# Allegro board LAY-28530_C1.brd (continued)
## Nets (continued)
EC1_RXD0: R59.2 U21.V2(EC1_RXD0/GPIO3_21)
EC1_RXD1: R55.2 U21.V1(EC1_RXD1/GPIO3_20)
EC1_RXD1/CFG_MODE0: R55.1 R214.2 U5.25(RXD1/CFG_MODE0)
EC1_RXD2: R53.2 U21.U1(EC1_RXD2/GPIO3_19)
EC1_RXD2/CFG_MODE1: R53.1 R210.2 U5.24(RXD2/CFG_MODE1)
EC1_RXD3: R49.2 U21.T2(EC1_RXD3/GPIO3_18)
EC1_RXD3/CFG_MODE2: R49.1 R207.2 U5.23(RXD3/CFG_MODE2)
EC1_TXC: R285.1 U5.21(TXC)
EC1_TXCTL: R288.1 U5.20(TXCTL)
EC1_TXD0: R296.1 U5.19(TXD0)
EC1_TXD1: R287.1 U5.18(TXD1)
EC1_TXD2: R295.1 U5.17(TXD2)
EC1_TXD3: R286.1 U5.16(TXD3)
EC1_VDDREG: C235.2 C251.1 R225.2 U5.31(VDD_REG)
EMI1_MDC: R27.2 R43.2 R277.1 U21.W2(EMI1_MDC/GPIO3_08)
EMI1_MDIO: R37.2 R46.2 R279.2 U21.Y1(EMI1_MDIO/GPIO3_09)
EMI2_MDC: R227.1 U8.J18(MDC) U21.P3(EMI2_MDC)
EMI2_MDIO: R229.1 U8.L18(MDIO) U21.P4(EMI2_MDIO)
EMMC_CLK: U32.2(I0A) U39.M6(CLK)
EMMC_CMD: U32.5(I0B) U39.M5(CMD)
EMMC_D0: U32.11(I0C) U39.A3(DAT0)
EMMC_D1: U32.14(I0D) U39.A4(DAT1)
EMMC_D2: U33.2(I0A) U39.A5(DAT2)
EMMC_D3: U33.5(I0B) U39.B2(DAT3)
EMMC_RST: Q13.3(COLLECTOR) R184.1 U39.K5(R\S\T\)
EMMC_SEL_N: Q12.3(COLLECTOR) R172.1 U32.1(S) U33.1(S)
EVDD: C81.1 C82.1 C113.1 C142.2 C149.1 C152.1 C320.1 C349.1 J16.4(VDD) Q7.3(S2) Q21.1(S2) R157.1 R158.1 R159.1 R160.1 R161.1 R162.1 R179.2 R184.2 R240.2 U21.K8(EVDD) U39.C6(VCCQ1) U39.M4(VCCQ3) U39.N4(VCCQ5) U39.P3(VCCQ4) U39.P5(VCCQ2)
GPIO1_14_EMMC_SEL_N: Q12.2(EMITTER) Q29.2(EMITTER) Q30.2(EMITTER) R290.1 SW3.3 U21.C17(RTC/GPIO1_14)
GPIO3_0_WAKE_L: P2.1(WAKE#) R289.2 R431.1 R432.1
GPIO3_1_CLKREQ_L: P2.7(CLKREQ#) R421.1 U21.AA3(TSEC_1588_TRIG_IN1/GPIO3_01/EC2)
GPIO3_2_WAKE_L: P3.1(WAKE#) R420.1 U21.AA1(EC2_GTX_CLK125/GPIO3_02/TSEC_15)
GPIO3_3_CLKREQ_L: P3.7(CLKREQ#) R422.1 U21.AB2(TSEC_1588_ALARM_OUT1/GPIO3_03/E)
I2C1_SCL: J14.1 R265.2 R418.1 U10.6(SCL) U13.6(SCL) U21.N1(IIC1_SCL) U38.54(SCL)
I2C1_SDA: J14.3 R260.2 R417.1 U10.5(SDA) U13.5(SDA) U21.N2(IIC1_SDA) U38.53(SDA)
I2C2_SCL: R264.2 R415.1 U21.M1(GPIO4_27/IIC2_SCL) U42.5(SCL) U47.5(SCL) U48.14(SCL)
I2C2_SDA: R259.2 R416.1 U21.M2(GPIO4_28/IIC2_SDA) U42.4(SDA) U47.4(SDA) U48.15(SDA)
IFC_A0: U20.31(A0) U25.23(2Q8)
IFC_A1: U20.26(A1) U25.22(2Q7)
IFC_A2: U20.25(A2) U25.20(2Q6)
IFC_A3: U20.24(A3) U25.19(2Q5)
IFC_A4: U20.23(A4) U25.17(2Q4)
IFC_A5: U20.22(A5) U25.16(2Q3)
IFC_A6: U20.21(A6) U25.14(2Q2)
IFC_A7: U20.20(A7) U25.13(2Q1)
IFC_A8: U20.10(A8) U25.12(1Q8)
IFC_A9: U20.9(A9) U25.11(1Q7)
IFC_A10: U20.8(A10) U25.9(1Q6)
IFC_A11: U20.7(A11) U25.8(1Q5)
IFC_A12: U20.6(A12) U25.6(1Q4)
IFC_A13: U20.5(A13) U25.5(1Q3)
IFC_A14: U20.4(A14) U25.3(1Q2)
IFC_A15: U20.3(A15) U25.2(1Q1)
IFC_A16: R299.1 SW2.5 U20.54(A16) U21.C7(IFC_A16)
IFC_A17: R292.1 SW2.6 U20.19(A17) U21.D7(IFC_A17)
IFC_A18: R304.1 SW2.3 U20.18(A18) U21.C8(IFC_A18)
IFC_A19: R302.1 SW2.4 U20.11(A19) U21.D8(IFC_A19)
IFC_A20: R308.1 U20.12(A20) U21.C9(IFC_A20)
IFC_A21: R315.2 U20.15(A21) U21.D9(IFC_A21/CFG_DRAM_TYPE)
IFC_A22: U20.2(A22) U21.C10(IFC_A22)
IFC_A23: U21.D10(IFC_A23) U27.1(A)
IFC_A23_INVERT: R140.2 SW3.7 U27.2(B) U48.6(P2)
IFC_A24: U21.C11(IFC_A24) U24.1(A)
IFC_A24_INVERT: R138.2 SW3.6 U24.2(B) U48.5(P1)
IFC_A25: R467.1 U21.D11(IFC_A25/GPIO2_25/I\F\C\_\W\P\1\) U23.1(A)
IFC_A25_INVERT: R135.2 SW3.5 U23.2(B) U48.4(P0)
IFC_A26: R468.1 U21.C12(IFC_A26/GPIO2_26/I\F\C\_\W\P\2\)
IFC_AD0: U16.J8(I/O7) U20.35(DQ0) U21.B6(IFC_AD00/CFG_GPINPUT0) U25.26(2D8)
IFC_AD1: U16.K7(I/O6) U20.37(DQ1) U21.A6(IFC_AD01/CFG_GPINPUT1) U25.27(2D7)
IFC_AD2: U16.J7(I/O5) U20.39(DQ2) U21.A7(IFC_AD02/CFG_GPINPUT2) U25.29(2D6)
IFC_AD3: U16.K6(I/O4) U20.41(DQ3) U21.B8(IFC_AD03/CFG_GPINPUT3) U25.30(2D5)
IFC_AD4: U16.K5(I/O3) U20.44(DQ4) U21.A8(IFC_AD04/CFG_GPINPUT4) U25.32(2D4)
IFC_AD5: U16.K4(I/O2) U20.46(DQ5) U21.B9(IFC_AD05/CFG_GPINPUT5) U25.33(2D3)
IFC_AD6: U16.J4(I/O1) U20.48(DQ6) U21.A9(IFC_AD06/CFG_GPINPUT6) U25.35(2D2)
IFC_AD7: U16.H4(I/O0) U20.50(DQ7) U21.A10(IFC_AD07/CFG_GPINPUT7) U25.36(2D1)
IFC_AD8: R245.2 SW1.1 U20.36(DQ8) U21.B11(IFC_AD08/CFG_RCW_SRC0) U25.37(1D8)
IFC_AD9: R251.2 SW1.2 U20.38(DQ9) U21.A11(IFC_AD09/CFG_RCW_SRC1) U25.38(1D7)
IFC_AD10: R253.2 SW1.3 U20.40(DQ10) U21.B12(IFC_AD10/CFG_RCW_SRC2) U25.40(1D6)
IFC_AD11: R255.2 SW1.4 U20.42(DQ11) U21.A12(IFC_AD11/CFG_RCW_SRC3) U25.41(1D5)
IFC_AD12: R257.2 SW1.5 U20.45(DQ12) U21.A13(IFC_AD12/CFG_RCW_SRC4) U25.43(1D4)
IFC_AD13: R262.2 SW1.6 U20.47(DQ13) U21.B14(IFC_AD13/CFG_RCW_SRC5) U25.44(1D3)
IFC_AD14: R268.2 SW1.7 U20.49(DQ14) U21.A14(IFC_AD14/CFG_RCW_SRC6) U25.46(1D2)
IFC_AD15: R276.2 SW1.8 U20.51(DQ15) U21.B15(IFC_AD15/CFG_RCW_SRC7) U25.47(1D1)
IFC_AVD: R321.2 SW2.8 U16.C4(ALE) U21.C15(IFC_AVD) U25.25(2LE) U25.48(1LE)
IFC_CLE: SW2.1 U16.D5(CLE) U21.C16(CFG_RCW_SRC8/IFC_CLE)
IFC_CS0: R317.1 U15.4(YA) U21.F13(I\F\C\_\C\S\0\)
IFC_CS1: R319.1 U15.7(YB) U21.E14(GPIO2_10/I\F\C\_\C\S\1\)
IFC_OE_N: R324.2 SW3.1 U16.D4(R\E\) U20.34(O\E\) U21.D15(I\F\C\_\O\E\)
IFC_RB0: R314.1 U15.11(I0C) U15.13(I1D) U21.F12(I\F\C\_\R\B\0\)
IFC_RB1: R312.1 U15.10(I1C) U15.14(I0D) U21.E11(I\F\C\_\R\B\1\)
IFC_TE: SW2.2 U21.A15(CFG_IFC_TE/IFC_TE)
IFC_WE_N: R310.2 R402.1 U16.C7(W\E\) U20.13(W\E\) U21.F11(CFG_ENG_USE0/I\F\C\_\W\E\0\)
IFC_WP_N: SW3.2 U21.D16(I\F\C\_\W\P\0\)
INTVCC: C71.1 D8.A R80.2 R92.1 R93.2 U9.3(MODE) U9.21(INTVCC)
JTAG_TCK: U21.E18(TCK) U44.10(B3)
JTAG_TDI: U21.C18(TDI) U44.12(B1)
JTAG_TDO: U21.D17(TDO) U44.11(B2)
JTAG_TMS: U21.E17(TMS) U44.9(B4)
LANEA_RX_N: C365.2 P3.23(PERN0)
LANEA_RX_P: C377.2 P3.25(PERP0)
LANEA_TX_N: C344.1 P3.31(PETN0)
LANEA_TX_P: C355.1 P3.33(PETP0)
LANEB_RX_N: C366.2 U8.V6(TX_LN2_N)
LANEB_RX_P: C381.2 U8.U6(TX_LN2_P)
LANEB_TX_N: C56.1 U21.Y11(SD1_TX1_N)
LANEB_TX_P: C57.1 U21.W11(SD1_TX1_P)
LANEC_RX_N: C427.2 P2.23(PERN0)
LANEC_RX_P: C409.2 P2.25(PERP0)
LANEC_TX_N: C403.1 P2.31(PETN0)
LANEC_TX_P: C391.1 P2.33(PETP0)
LANED_RX_N: C30.1 U21.AB14(SD1_RX3_N)
LANED_RX_P: C37.1 U21.AC14(SD1_RX3_P)
LANED_TX_N: C417.1 U6.39(HSIN)
LANED_TX_P: C429.1 U6.38(HSIP)
LDO_1V0: C98.1 FL1.3(OUT_IN) R137.2 R309.2 U26.3(OUT1) U26.4(OUT2)
LED_G-: C18.1 J3.16(LEDG1-) J24.17(GRN-1) R26.2
LED_GY+: J3.17(LEDG1+) J3.19(LEDG-) J24.18(GRN+) J24.20(GRN-2) L10.2
LED_Y-: C16.1 J3.18(LEDY-) J24.19(YEL-) R24.2
MPCIE1_CLK+: P3.13(REFCLK+) R351.2 R352.1
MPCIE1_CLK-: P3.11(REFCLK-) R357.2 R358.1
MPCIE2_CLK+: P2.13(REFCLK+) R333.2 R334.1
MPCIE2_CLK-: P2.11(REFCLK-) R347.2 R348.1
NAND_BOOT_SEL: R291.2 SW3.4 U15.1(S)
NAND_CS: U15.3(I1A) U15.5(I0B) U16.C6(C\E\)
NAND_RB: U15.12(YD) U16.C8(R/B\)
NOR_CS: U15.2(I0A) U15.6(I1B) U20.32(C\E\)
NOR_RB: U15.9(YC) U20.17(RY/B\Y\)
NUART_CTS: L3.2 P1.8
NUART_RTS: L5.2 P1.1
PCIE_3V3: C300.1 C306.1 C307.1 C308.1 P2.2(3.3V_1) P2.24(+3.3VAUX) P2.39(RESERVED4) P2.41(RESERVED5) P2.52(3.3V_2) Q23.2(SOURCE) R246.2 R249.1
POE_12V: D10.A L13.2 Q4.4(D2) R61.1 R235.2
PORESET: Q24.3(COLLECTOR) Q25.3(COLLECTOR) R356.2 U21.B5(P\O\R\E\S\E\T\)
RESET: P2.22(PERST#) P3.22(PERST#) Q11.2(EMITTER) Q13.2(EMITTER) Q14.2(EMITTER) Q15.2(EMITTER) Q25.2(EMITTER) R15.1 U3.2(R\E\S\E\T\) U5.13(P\H\Y\R\S\T\) U6.13(P\H\Y\R\S\T\)
RS232_CTS0: L3.1 U2.8(R2IN)
RS232_RTS0: L5.1 U2.7(T2OUT)
RS232_RXD0: L6.1 U2.13(R1IN)
RS232_TXD0: L7.1 U2.14(T1OUT)
RTC_INT_N: R86.2 U10.7(SQW/\I\N\T\) U21.R4(IRQ5/GPIO1_25)
RTC_XI: U10.1(X1) Y4.1
RTC_XO: U10.2(X2) Y4.2
SD_CLK: J16.5(CLK) U30.1(P1) U30.8(NC8) U32.3(I1A)
SD_CLK1_N: R113.2 R114.1 U21.AB7(SD1_REF_CLK1_N)
SD_CLK1_P: R110.2 R111.1 U21.AC7(SD1_REF_CLK1_P)
SD_CLK2_N: R121.2 R122.1 U21.AB16(SD1_REF_CLK2_N)
SD_CLK2_P: R116.2 R117.1 U21.AC16(SD1_REF_CLK2_P)
SD_CMD: J16.2(CMD) U30.2(P2) U30.7(NC7) U32.6(I1B)
SD_D0: J16.7(DAT0) U30.3(P3) U30.6(NC6) U32.10(I1C)
SD_D1: J16.8(DAT1) U30.4(P4) U30.5(NC5) U32.13(I1D)
SD_D2: J16.9(DAT2) U31.1(P1) U31.8(NC8) U33.3(I1A)
SD_D3: J16.1(DAT3) U31.2(P2) U31.7(NC7) U33.6(I1B)
SDHC_CD_N: J16.3A(C\D\) Q29.3(COLLECTOR) R156.1 U21.H3(S\D\H\C\_\C\D\/GPIO4_24/IIC3_SC) U31.3(P3) U31.6(NC6)
SDHC_CLK: R160.2 R282.1 U32.4(YA)
SDHC_CMD: R159.2 U21.J2(SDHC_CMD/GPIO2_04/D\M\A\1\_\D\R) U32.7(YB)
SDHC_D0: R158.2 U21.J1(SDHC_DAT0/GPIO2_05/D\M\A\1\_\D\) U32.9(YC)
SDHC_D1: R157.2 U21.K2(SDHC_DAT1/GPIO2_06/D\M\A\1\_\D\) U32.12(YD)
SDHC_D2: R162.2 U21.K1(SDHC_DAT2/GPIO2_07/D\M\A\2\_\D\) U33.4(YA)
SDHC_D3: R161.2 U21.L1(SDHC_DAT3/GPIO2_08/D\M\A\2\_\D\) U33.7(YB)
SDHC_VS: R266.1 R270.2 U21.C5(IRQ1/SDHC_VS/USBCLK)
SDHC_WP_N: J16.10(WP) Q30.3(COLLECTOR) R155.1 U21.H4(SDHC_WP/GPIO4_25/IIC3_SDA) U31.4(P4) U31.5(NC5)
SGMII_AVDD10: C199.2 C200.2 C214.2 R64.2 U6.4(AVDD10_1) U6.9(AVDD10_2) U6.47(AVDD10_3)
SGMII_DVDD10: C221.2 R71.2 U6.22(DVDD10)
SGMII_DVDD_3V3: C230.2 C241.1 R58.2 R218.2 R220.2 U6.30(DVDD33)
SGMII_DVDDRG: C228.2 C233.1 R56.2 R67.2 R69.2 U6.29(DVDD_RG)
SGMII_LED0/PHYAD0: C20.1 C603.1 D13.4(CATHODE1) J5.17 R58.1 U6.35(LED0/PHYAD0)
SGMII_LED1/CFG_LDO0: R32.1 R213.2 R394.1 U6.36(LED1/CFG_LDO0)
SGMII_LED2/CFG_LDO1: R218.1 U6.37(LED2/CFG_LDO1)
SGMII_MDIN0: J5.10 U6.3(MDIN0)
SGMII_MDIN1: J5.5 U6.6(MDIN1)
SGMII_MDIN2: J5.2 U6.8(MDIN2)
SGMII_MDIN3: J5.9 U6.11(MDIN3)
SGMII_MDIP0: J5.11 U6.2(MDIP0)
SGMII_MDIP1: J5.4 U6.5(MDIP1)
SGMII_MDIP2: J5.3 U6.7(MDIP2)
SGMII_MDIP3: J5.8 U6.10(MDIP3)
SGMII_PHY_INT_N: R272.2 U6.34(I\N\T\/P\M\E\) U21.D5(IRQ0)
SGMII_RXC/PHYAD1: R67.1 U6.28(RXC/PHYAD1)
SGMII_RXCTL/PHYAD2: R68.2 U6.27(RXCTL/PHYAD2)
SGMII_RXD1/CFG_MODE0: R69.1 U6.25(RXD1/CFG_MODE0)
SGMII_RXD2/CFG_MODE1: R56.1 U6.24(RXD2/CFG_MODE1)
SGMII_RXD3/CFG_MODE2: R51.2 U6.23(RXD3/CFG_MODE2)
SGMII_VDDREG: C234.2 C250.1 R223.2 U6.31(VDD_REG)
SPI_CLK: R99.2 U14.16(SCK)
SPI_CS: R238.1 U14.7(C\S\) U21.J4(SDHC_DAT4/GPIO2_00/S\P\I\_\C\S\)
SPI_MISO: U14.8(SO/IO1) U21.M3(SPI_MISO)
SPI_MOSI: U14.15(SI/IO0) U21.M4(SPI_MOSI)
SYS_REFCLK_N: R108.2 R109.1 U21.B4(D\I\F\F\_\S\Y\S\C\L\K\)
SYS_REFCLK_P: R106.2 R107.1 U21.A4(DIFF_SYSCLK)
TEST_SEL_N: R283.2 SW3.8 U21.F8(T\E\S\T\_\S\E\L\)
TRCT: C176.2 C179.2 C180.1 C185.1 C187.2 C191.2 C192.2 J3.1(TRCT2) J3.6(TRCT3) J3.7(TRCT1) J3.12(TRCT4) J3.13(CMCT) J24.1(TRCT2) J24.6(TRCT3) J24.7(TRCT1) J24.12(TRCT4)
UART1_CTS: R6.1 U2.9(R2OUT) U21.R3(GPIO1_21/U\A\R\T\1\_\C\T\S\/UAR)
UART1_RTS: R7.1 U2.10(T2IN) U21.R2(GPIO1_19/U\A\R\T\1\_\R\T\S\/UAR)
UART1_RXD: U2.12(R1OUT) U21.P1(GPIO1_17/UART1_SIN)
UART1_TXD: U2.11(T1IN) U21.R1(GPIO1_15/UART1_SOUT)
UART_SIN: L6.2 P1.6
UART_SOUT: L7.2 P1.3
VCORE_EN: C597.1 R320.1 R327.1 U22.4(EN/UV) U26.9(S\H\D\N\) U38.26(LDO2)
VPA: C622.1 C623.1 C624.1 C630.1 C632.1 C634.1 C639.1 C643.1 L30.2 P2.45(RESERVED7) P2.47(RESERVED8) P2.49(RESERVED9) P2.51(RESERVED10) R434.1 U45.22(BIAS)
VPA_PCIE2: C626.1 C627.1 C628.1 C648.1 C649.1 C651.1 C653.1 C658.1 L31.2 P3.45(RESERVED7) P3.47(RESERVED8) P3.49(RESERVED9) P3.51(RESERVED10) R469.1 U49.22(BIAS)
VR500_1V5: C116.1 C122.1 C130.1 C132.1 C321.1 C322.1 C324.1 C326.1 C456.1 C457.1 C458.1 C463.1 L22.1 P2.6(1.5V_1) P2.28(1.5V_2) P2.48(1.5V_3) P3.6(1.5V_1) P3.28(1.5V_2) P3.48(1.5V_3) U38.13(FB1)
N17321635: Q9.2(EMITTER) R143.1 U21.E16(C\K\S\T\P\_\O\U\T\)
N17423556: J13.6 R370.2
N23886013: C5.1 U2.2(V+)
N23886021: C8.2 U2.3(C1-)
N23886023: C8.1 U2.1(C1+)
N23886031: C3.1 U2.6(V-)
N23886069: C4.2 U2.4(C2+)
N23886074: C4.1 U2.5(C2-)
N23887688: BT1.1(POS1) BT1.2(POS2) C60.1 R84.2
N24081686: L22.2 U38.8(LX1_1) U38.9(LX1_2) U38.11(LX1_3)
N24082962: L24.2 U38.22(LX2)
N24084401: L21.1 U38.35(LX3_1) U38.36(LX3_2)
N24085678: L23.1 U38.21(LX4)
N24088889: TP19.1(PIN1) U38.39(LDO4)
N24089783: C145.2 C147.1 U38.29(VHALF)
N24092126: C125.1 U38.51(VDIG)
N24092316: C126.1 U38.49(VCC)
N24092557: C124.1 U38.52(VBG)
N24092669: C129.1 U38.43(VBIAS)
N24105172: C1.1 C2.1 D1.C D2.C D3.C D4.C D23.C L9.1 R189.1 U1.32(VPORTP)
N24105186: C1.2 D19.A D20.A D21.A D22.A D23.A R185.1 U1.1(SHDN) U1.5(VPORTN1) U1.6(VPORTN2)
N24105908: R185.2 U1.3(RCLASS)
N24106035: C181.1 R189.2 R192.1 TP3.1(PIN1) U1.18(UVLO) U1.29(PWRGD)
N24106207: R1.1 R2.2 U1.16(FB)
N24106733: C170.1 C175.1 R187.2 R188.2 U1.10(VCC)
N24106981: C183.1 L9.2 R188.1 R195.1 T2.5
N24107203: R14.1 U1.24(PG)
N24107357: C177.2 C178.2 U1.17(VCMP)
N24107470: R196.1 U1.9(SG)
N24107483: C188.1 R196.2
N24107486: C188.2 T1.1
N24107616: C208.1 T1.6
N24107621: C208.2 D25.3(CATHODE) R204.2 R208.2
N24107777: Q3.4(GATE) Q17.2(E) Q18.2(EMITTER)
N24107780: Q17.1(B) Q18.1(BASE) R208.1
N24107840: C40.1 Q18.3(COLLECTOR) R47.2 R61.2
N24107947: D7.C R47.1
N24107950: D7.A Q3.5(DRAIN_1) Q3.6(DRAIN_2) Q3.7(DRAIN_3) Q3.8(DRAIN_4) R42.1 T2.6
N24108405: C27.1 R42.2
N24108768: C28.1 C38.1 L13.1 T2.10
N24108952: Q2.1(SOURCE_1) Q2.2(SOURCE_2) Q2.3(SOURCE_3) R13.1 U1.20(SENSE+)
N24109652: C184.1 U1.21(CCMP)
N24109671: R191.1 U1.22(RCMP)
N24109742: R3.1 U1.12(ENDLY)
N24109897: C173.1 U1.15(OSC)
N24109974: R190.1 U1.23(PGDLY)
N24109983: R4.1 U1.11(TON)
N24110294: C174.1 U1.14(SFST)
N24133241: F1.1 J1.1 R5.1
N24137908: C89.1 U22.21(INTVCC)
N24137912: C405.2 L18.1 U22.15(SW1) U22.16(SW2) U22.17(SW3) U22.18(SW4) U22.19(SW5)
N24137946: C405.1 U22.20(BST)
N24137962: C87.2 R127.2 R128.1 U22.24(FB)
N24138040: R129.1 U22.3(RT)
N24138143: C88.1 U22.2(TR/SS)
N24145679: C302.1 C305.1 C309.1 C314.1 C318.1 C325.1 C327.1 L26.1 R105.1 U19.10(VDDO4) U19.15(VDDO3) U19.18(VDDO2) U19.21(VDDO1) U19.23(VDDO0)
N24145732: C313.1 C319.1 R263.2 U19.5(VDDA)
N24145752: C303.1 C304.1 L25.2 R263.1 U19.22(VDDD)
N24151368: C86.1 R112.2 U19.4(XIN/REF) Y5.1
N24151377: C85.1 R112.1 U19.3(XOUT) Y5.3
N24157795: R104.2 R105.2 U19.24(OUT0_SEL_I2CB)
N24157798: J12.3 R125.1 R126.1 U19.8(SEL1/SDA)
N24157984: R106.1 U19.20(OUT1_P)
N24157991: R108.1 U19.19(OUT1_N)
N24158001: R113.1 U19.16(OUT2_N)
N24158003: R110.1 U19.17(OUT2_P)
N24158101: R116.1 U19.14(OUT3_P)
N24158103: R121.1 U19.13(OUT3_N)
N24158105: R124.1 U19.12(OUT4_N)
N24158107: R123.1 U19.11(OUT4_P)
N24158224: R123.2 R345.1 U43.3(CLK0)
N24158233: R124.2 R350.1 U43.4(NCLK0)
N24158614: J12.1 R115.1 R119.1 U19.9(SEL0/SCL)
N24164336: R355.1 U43.8(IREF)
N24164341: R335.1 U43.2(CLK_SEL)
N24164581: R333.1 U43.14(Q0)
N24164584: R347.1 U43.13(NQ0)
N24164587: R351.1 U43.12(Q1)
N24164590: R357.1 U43.11(NQ1)
N24169528: R85.2 R87.1 U11.7(SENSE/ADJ)
N24185665: C57.2 U8.U4(RX_LN2_P)
N24185672: C56.2 U8.V4(RX_LN2_N)
N24186431: R222.2 U8.N17(R\X\_\D\C\_\R\S\T\)
N24186507: R209.2 U8.F5(TX_EN)
N24186703: R201.2 U8.J4(R\S\T\)
N24186832: C31.1 U8.F18(XTAL_I) Y3.1
N24187101: R52.2 U8.G18(XTAL_O)
N24187104: J7.1 U8.L14(TDI)
N24187111: J7.2 U8.M16(TMS)
N24187118: J7.3 U8.K14(TCK)
N24187125: J7.4 R202.1 U8.M15(T\R\S\T\)
N24187168: J7.5 U8.L15(TDO)
N24187336: R20.2 U8.A10(RREF_BG)
N24187387: R203.1 U8.F17(X\T\A\L\_\S\E\L\E\C\T\)
N24187390: R21.1 U8.G13(50M_CLK_TERM)
N24187475: R212.1 U8.H3(R\S\T\_\O\U\T\)
N24187514: J8.3 R75.1 U8.H18(SMB_DAT)
N24187517: J8.1 R76.1 U8.H17(SMB_CLK)
N24187752: R219.1 U8.K15(ADDR0)
N24187759: R205.1 U8.J15(ADDR1)
N24187766: R215.1 U8.J16(ADDR2)
N24187780: R211.1 U8.H16(ADDR3)
N24187787: R206.1 U8.G17(ADDR4)
N24189801: R228.1 U8.K18(I\N\T\)
N24194949: C64.1 C78.1 C269.1 C275.1 C276.2 C277.1 C278.1 C280.2 L17.1 U8.R5(VDD_SRDS1) U8.T8(VDD_SRDS4) U8.T10(VDD_SRDS2) U8.T12(VDD_SRDS3)
N24197224: C65.1 C273.1 C274.1 C279.2 U8.T4(P0_VREG_SRDS1) U8.T6(P0_VREG_SRDS2)
N24197929: C13.1 C212.2 L8.1 U8.E10(AFE_DVDD)
N24198270: C17.1 C213.2 L12.1 U8.E18(VA22_XTAL)
N24220381: C347.1 C356.2 C357.2 C358.1 C359.1 L28.1 U21.G8(USB_SVDD1) U21.H8(USB_SVDD2)
N24221237: C334.1 C335.2 C336.2 C337.1 C343.1 L27.1 U21.D4(USB_HVDD1) U21.G7(USB_HVDD2)
N24221789: C361.1 C371.1 C401.2 C402.2 C404.1 L29.1 U21.H9(USB_OVDD1) U21.H10(USB_OVDD2)
N24222945: TP44.1(PIN1) U21.G16(SENSEVDD)
N24222963: TP36.1(PIN1) U21.F16(SENSEGND)
N24242061: C338.1 J10.1 R98.1 U21.H5(PROG_SFP)
N24242100: C340.1 J11.2 R101.1 U21.K5(PROG_MTR)
N24244080: R346.1 U21.H18(FA_VL)
N24245830: C384.1 C390.1 C419.1 C422.2 C423.2 C425.1 FL1.1(IN_OUT) U21.T11(S1VDD1) U21.T12(S1VDD2) U21.T13(S1VDD3)
N24247836: C375.1 C382.1 C389.1 C406.1 C426.1 C450.1 C451.2 C452.2 FL2.1(IN_OUT) U21.V10(X1VDD1) U21.V11(X1VDD2) U21.V12(X1VDD3) U21.V13(X1VDD4) U21.V14(X1VDD5)
N24271003: C315.1 C333.1 R273.2 U21.H6(AVDD_CGA1)
N24271010: C316.1 C342.1 R274.2 U21.J6(AVDD_PLAT)
N24271066: C449.1 C462.1 R331.2 U21.L17(AVDD_D1)
N24275030: C328.1 C329.1 C330.1 R294.1 U21.Y7(AVDD_SD1_PLL1)
N24275210: C464.1 C465.1 C467.1 R330.1 U21.Y16(AVDD_SD1_PLL2)
N24275332: C328.2 C329.2 C330.2 R305.1
N24275468: C464.2 C465.2 C467.2 R336.1
N24288324: C203.2 C206.2 R225.1 R226.2 U5.1(AVDD33_1) U5.12(AVDD33_2)
N24289313: C48.1 C51.2 L14.2 R66.1 R74.1
N24289334: L14.1 U5.32(REG_OUT)
N24291582: C36.1 R40.1 U5.45(XTAL_IN) Y2.1
N24291591: C26.1 R40.2 U5.46(XTAL_OUT/EXT_CLK) Y2.3
N24291955: R59.1 R217.1 U5.26(RXD0/RXDLY)
N24292790: R30.2 U5.48(RSET)
N24294529: D12.2(ANODE1) R401.2
N24294558: C607.1 D12.1(ANODE2) R396.2
N24301989: C201.2 C202.2 R223.1 R224.2 U6.1(AVDD33_1) U6.12(AVDD33_2)
N24302177: C46.1 C50.2 L15.2 R64.1 R71.1
N24302183: L15.1 U6.32(REG_OUT)
N24302493: C33.1 R39.1 U6.45(XTAL_IN) Y1.1
N24302533: C25.1 R39.2 U6.46(XTAL_OUT/EXT_CLK) Y1.3
N24302727: R28.2 U6.48(RSET)
N24303060: D13.2(ANODE1) R395.2
N24303062: C604.1 D13.1(ANODE2) R394.2
N24307470: C37.2 U6.40(HSOP)
N24307585: C30.2 U6.41(HSON)
N24320723: R278.2 R288.2 U21.W3(EC1_TX_EN/GPIO3_15)
N24320726: C331.1 R285.2 U21.T4(EC1_GTX_CLK/GPIO3_16)
N24320797: R296.2 U21.V5(EC1_TXD0/GPIO3_14)
N24320800: R287.2 U21.V3(EC1_TXD1/GPIO3_13)
N24320803: R295.2 U21.U4(EC1_TXD2/GPIO3_12)
N24320806: R286.2 U21.U3(EC1_TXD3/GPIO3_11)
N24322101: R50.1 U5.44(CLKOUT)
N24325827: R342.2 U21.V23(D1_MDIC0)
N24331550: R371.2 U37.B9(ZQ)
N24334551: R339.2 U21.M23(D1_MECC0)
N24334558: R338.2 U21.N23(D1_MECC1)
N24334565: R340.2 U21.R22(D1_MECC2)
N24334572: R341.2 U21.T23(D1_MECC3)
N24340384: R372.2 U36.B9(ZQ)
N24342556: R374.2 U35.B9(ZQ)
N24344964: R373.2 U34.B9(ZQ)
N24364084: R301.1 U20.16(W\P\)
N24368311: R243.1 U16.C3(W\P\)
N24370219: R239.1 U14.9(W\P\/IO2)
N24370226: R237.1 U14.1(H\O\L\D\/IO3)
N24371075: R282.2 U21.H1(SDHC_CLK/GPIO2_09/D\M\A\2\_\D\D)
N24377296: C140.1 C141.1 U39.C2(VDDI)
N24378188: L4.4 U21.D1(USB1_UDP)
N24378195: L4.1 U21.D2(USB1_UDM)
N24378208: J2.A3(DATA-) L4.3 U40.1(A1)
N24378216: J2.A2(DATA+) L4.2 U40.3(A3)
N24378377: J2.A1(VCC) L1.2 U40.5(A5)
N24378560: J2.A4(GND) L2.2
N24378635: C323.1 R298.2 U21.E3(USB_IBIAS_REXT)
N24378650: C323.2 R284.1
N24378685: R271.1 U21.C3(USB1_UID)
N24379174: R199.1 U21.E4(USB1_PWRFAULT)
N24379185: R25.1 U4.2(ONA) U21.F4(USB1_DRVVBUS)
N24379468: C11.1 C12.1 C14.1 D5.C(CATHODE) L1.1 R11.1 U4.10(OUTA)
N24379558: D5.A(ANODE) R10.1 R11.2 U21.B2(USB1_VBUSCLMP)
N24379631: R22.2 U4.9(F\L\T\A\)
N24380059: R19.1 U4.3(ISET)
N24380394: C193.2 Q16.3(COLLECTOR) R198.1 R199.2
N24389900: R297.1 U21.A5(GPIO1_13/ASLEEP)
N24390647: R323.2 U21.F9(S\C\A\N\_\M\O\D\E\)
N24391453: R328.2 U21.F19(T\M\P\_\D\E\T\E\C\T\)
N24392141: Q10.3(COLLECTOR) R163.2 R164.2 U21.F18(T\R\S\T\)
N24402189: Q8.3(COLLECTOR) R150.2 U21.E8(H\R\E\S\E\T\)
N24414694: TP2.1(PIN1) U1.30(P\W\R\G\D\)
N24414710: TP1.1(PIN1) U1.2(T\2\P\)
N24418365: Q24.1(BASE) R367.2
N24421074: R244.2 SW1.16
N24421076: R250.2 SW1.15
N24421078: R252.2 SW1.14
N24421080: R254.2 SW1.13
N24421082: R256.2 SW1.12
N24421084: R261.2 SW1.11
N24421086: R267.2 SW1.10
N24421088: R275.2 SW1.9
N24421090: R293.2 SW2.16
N24421092: R300.2 SW2.15
N24421094: R303.2 SW2.14
N24421096: R307.2 SW2.13
N24421098: R313.2 SW2.11
N24421100: R311.2 SW2.12
N24421104: R318.2 SW2.9
N24422044: TP41.1(PIN1) U21.E7(CLK_OUT)
N24422127: R337.1 U21.H19(FA_ANALOG_G_V)
N24422137: R349.1 U21.J18(FA_ANALOG_PIN)
N24426897: R325.1 U21.C14(GPIO2_15/I\F\C\_\P\E\R\R\)
N24433996: R130.2 SW3.16
N24433998: R131.2 SW3.15
N24434000: R132.1 SW3.14
N24434027: R133.1 SW3.13
N24434063: R136.1 SW3.12
N24434090: R139.1 SW3.11
N24434117: R141.1 SW3.10
N24442993: R309.1 U21.W7(SD1_IMP_CAL_RX)
N24443017: R329.1 U21.V15(SD1_IMP_CAL_TX)
N24480234: R33.1 R38.1 U7.6(MODE/SYNC)
N24480259: C19.2 R33.2 R45.2 R54.2 U7.4(PGFB) U7.10(INTVCC)
N24480273: C217.1 L11.1 U7.7(SW)
N24480332: C41.1 R60.2 U7.1(ISET)
N24480366: R29.2 R36.2 U7.5(RUN)
N24480391: C217.2 U7.9(BOOST)
N24480399: R44.2 R45.1 U7.3(RT)
N24480593: C43.2 R48.2 R54.1 U7.2(ITH)
N24480595: C32.2 R48.1
N24506779: C478.1 U28.21(INTVCC)
N24506783: C474.2 L19.1 U28.15(SW1) U28.16(SW2) U28.17(SW3) U28.18(SW4) U28.19(SW5)
N24506809: C474.1 U28.20(BST)
N24506829: C106.2 R148.1 R149.2 U28.24(FB)
N24506871: R359.1 U28.3(RT)
N24506911: R145.1 R147.2 U28.4(EN/UV)
N24506929: C105.1 U28.2(TR/SS)
N24509763: C480.1 U29.21(INTVCC)
N24509767: C481.2 L20.1 U29.15(SW1) U29.16(SW2) U29.17(SW3) U29.18(SW4) U29.19(SW5)
N24509789: C481.1 U29.20(BST)
N24509805: C109.2 R151.1 R152.2 U29.24(FB)
N24509853: R361.1 U29.3(RT)
N24509885: R146.2 U29.4(EN/UV)
N24509913: C103.1 U29.2(TR/SS)
N24514524: TP12.1(PIN1) U22.23(PG)
N24515056: J18.2 R145.2
N24544266: TP50.1(PIN1) U38.3(P\O\R\)
N24551325: J6.1 R9.1 SW4.1
N24551347: C7.2 Q1.3(COLLECTOR) R8.2 R9.2 U3.3(M\R\)
N24582130: C377.1 U21.AC9(SD1_RX0_P)
N24582194: C366.1 U21.AB11(SD1_RX1_N)
N24582197: C381.1 U21.AC11(SD1_RX1_P)
N24582200: C365.1 U21.AB9(SD1_RX0_N)
N24582275: C355.2 U21.W9(SD1_TX0_P)
N24582286: C344.2 U21.Y9(SD1_TX0_N)
N24582369: C403.2 U21.Y13(SD1_TX2_N)
N24582387: C391.2 U21.W13(SD1_TX2_P)
N24582412: TP30.1(PIN1) U21.V8(SD1_PLL1_TPA)
N24582419: TP28.1(PIN1) U21.U10(SD1_PLL1_TPD)
N24582434: TP37.1(PIN1) U21.W16(SD1_PLL2_TPA)
N24582441: TP42.1(PIN1) U21.U14(SD1_PLL2_TPD)
N24584329: TP18.1(PIN1) U38.41(LDO5)
N24605281: TP57.1(PIN1) U38.1(I\N\T\)
N24616249: C44.1 R52.1 Y3.3
N24647838: Q25.1(BASE) R368.2
N24648256: Q10.1(BASE) R153.2
N24648262: Q11.1(BASE) R154.2
N24652945: Q4.1(G) Q5.1(G) Q20.3(COLLECTOR) R236.1
N24653996: Q19.4(G2) R230.1 R231.2
N24654004: Q6.1(G) Q19.5(D2-2) Q19.6(D2-1) R97.1
N24658856: R343.2 U21.Y23(D1_MDIC1)
N24665133: Q21.5(D2-2) Q21.6(D2-1) Q21.7(D2-2) Q21.8(D2-1)
N24674533: C288.2 Q7.2(G2) Q7.4(G2) Q22.4(G2) Q22.7(D2-2) Q22.8(D2-1) R241.2
N24674544: C289.2 Q21.2(G2) Q21.4(G2) Q22.5(D2-2) Q22.6(D2-1) R242.2
N24675233: Q22.2(G2) R258.2 R266.2
N24678302: Q23.1(GATE) R247.2 R248.2
N24861043: Q1.1(BASE) R16.2
N24873583: Q13.1(BASE) R179.1
N24876902: Q14.1(BASE) R194.1
N24877168: Q15.1(BASE) R193.2
N24891529: R269.2 U21.A3(SYSCLK)
N24891545: R353.2 U21.J17(DDRCLK)
N24892246: Q8.1(BASE) R142.2
N24892373: Q12.1(BASE) R165.2
N24932777: D24.1(ANODE1) R1.2 T2.1
N24935123: D24.3(CATHODE1) R187.1
N24935830: C186.2 Q2.5(DRAIN_1) Q2.6(DRAIN_2) Q2.7(DRAIN_3) Q2.8(DRAIN_4) T2.3
N24935853: C186.1 R195.2
N24936812: Q2.4(GATE) R14.2
N24970769: R83.1 R88.1 U12.7(SENSE/ADJ)
N24994453: R95.1 R96.2 U11.9(S\H\D\N\)
N24996629: Q4.3(S) Q5.3(S) R94.2
N25019525: C535.2 R379.1 R381.2
N25029315: C177.1 R186.2
N25032157: Q28.1(BASE) R297.2
N25032334: Q9.1(BASE) R144.1
N25072149: R118.2 U19.6(CLKSEL)
N25115909: C409.1 U21.AC13(SD1_RX2_P)
N25115912: C427.1 U21.AB13(SD1_RX2_N)
N25116015: C429.2 U21.W14(SD1_TX3_P)
N25116018: C417.2 U21.Y14(SD1_TX3_N)
N25118599: Q19.7(D2-2) Q19.8(D2-1) Q20.1(BASE) R235.1
N25120670: Q19.2(G2) R232.1 R234.1
N25139524: D14.2(ANODE1) R393.2
N25139526: D14.1(ANODE2) R392.2
N25141555: D15.C(CATHODE) R399.1
N25157671: J21.2 R79.2
N25157693: C61.2 R81.1 R82.2 U9.4(FB)
N25157716: C75.2 D8.C U9.20(BOOST)
N25157741: C75.1 L16.1 U9.11(SW1) U9.12(SW2) U9.13(SW3) U9.14(SW4) U9.15(SW5) U9.16(SW6)
N25157783: C67.1 R91.2 U9.19(SVIN)
N25157815: R78.1 R79.1 U9.7(RUN)
N25157819: C281.1 U9.5(TRACK/SS)
N25157835: R233.2 U9.1(RT)
N25157944: R89.2 R90.1 R92.2 R93.1 U9.2(PHMODE)
N25158030: C53.1 R77.1 R80.1 U9.6(ITH)
N25158044: C52.1 R77.2
N25168167: D18.C(CATHODE) Q28.3(COLLECTOR)
N25168313: D18.A(ANODE) R400.2
N25169246: Q16.1(BASE) R22.1 R23.1
N25171285: R27.1 U5.14(MDC)
N25171337: R43.1 U6.14(MDC)
N25171340: R46.1 U6.15(MDIO)
N25212963: R134.1 R137.1 U26.7(SENSE/ADJ)
N25235874: C22.1 J4.20 R31.2
N25235936: C189.1 J4.1 J4.6 J4.7 J4.12
N25236971: J4.18 R34.2
N25238548: C190.1 J5.1 J5.6 J5.7 J5.12
N25238664: J5.18 R35.2
N25239505: C23.1 J5.20 R32.2
N25263474: R354.2 U21.M17(D1_MVREF)
N25276538: R37.1 U5.15(MDIO)
N25435604: R99.1 U21.L3(SPI_CLK)
N25440106: Q11.3(COLLECTOR) R164.1
N25462949: R120.2 U19.7(SD/O\E\)
N25493237: TP17.1(PIN1) U28.23(PG)
N25495882: TP15.1(PIN1) U21.A17(IFC_CLK0)
N25614619: TP16.1(PIN1) U21.B17(IFC_CLK1)
N25614638: TP13.1(PIN1) U21.C13(IFC_NDDDR_CLK)
N25614641: TP31.1(PIN1) U21.E13(IFC_NDDQS)
N25614652: TP32.1(PIN1) U21.D12(IFC_A27/GPIO2_27/I\F\C\_\W\P\3\)
N25614663: TP43.1(PIN1) U21.P17(D1_TPA)
N25614680: TP35.1(PIN1) U21.F7(E\V\T\4\)
N25614695: TP39.1(PIN1) U21.E5(E\V\T\3\)
N25614710: TP33.1(PIN1) U21.E10(E\V\T\2\)
N25614762: TP40.1(PIN1) U21.D6(E\V\T\1\)
N25614777: TP38.1(PIN1) U21.C6(E\V\T\0\)
N25614880: TP59.1(PIN1) U21.M5(GPIO1_16/UART2_SOUT)
N25617432: TP34.1(PIN1) U21.F10(I\R\Q\_\O\U\T\/E\V\T\9\)
N25617574: TP24.1(PIN1) U21.AA5(TSEC_1588_PULSE_OUT2/GPIO3_07/E)
N25617577: TP5.1(PIN1) U21.AA2(GPIO3_26/EC2_TXD3)
N25617583: R424.2 R425.1 U21.AA4(TSEC_1588_ALARM_OUT2/GPIO3_04/E)
N25617586: R423.2 R426.1 U21.Y4(TSEC_1588_CLK_OUT/GPIO3_05/EC2_)
N25617589: TP8.1(PIN1) U21.AC3(TSEC_1588_PULSE_OUT1/GPIO3_06/E)
N25617590: TP11.1(PIN1) U21.AC5(GPIO3_24/EC2_RX_DV)
N25617591: TP9.1(PIN1) U21.AC4(GPIO3_28/EC2_RXD1)
N25617592: TP7.1(PIN1) U21.AB3(GPIO3_27/EC2_RXD3)
N25617593: TP10.1(PIN1) U21.AB5(GPIO3_25/EC2_RXD0)
N25622344: C644.2 R445.1 U42.10(VIN+)
N25622365: C644.1 R444.1 U42.9(VIN-)
N25675358: Q7.5(D2-2) Q7.6(D2-1) Q7.7(D2-2) Q7.8(D2-1)
N25696806: D11.A(ANODE) R102.2
N26207329: TP60.1(PIN1) U21.N3(GPIO1_22/UART4_SIN/E\V\T\8\/U\A)
N26207331: TP61.1(PIN1) U21.N4(GPIO1_20/UART4_SOUT/E\V\T\7\/U\)
N26207914: TP45.1(PIN1) U21.F14(GPIO2_11/I\F\C\_\C\S\2\)
N26207917: TP46.1(PIN1) U21.F15(GPIO2_12/I\F\C\_\C\S\3\)
N26208803: TP47.1(PIN1) U21.J3(SDHC_CMD_DIR/SDHC_DAT5/GPIO2_01)
N26208818: TP48.1(PIN1) U21.K4(SDHC_DAT0_DIR/SDHC_DAT6/GPIO2_0)
N26208833: TP49.1(PIN1) U21.K3(SDHC_DAT123_DIR/SDHC_CLK_SYNC_O)
N26318609: TP51.1(PIN1) U21.N5(GPIO1_18/UART2_SIN)
N26607524: D17.C(CATHODE) R397.1
N26607549: P2.44(LED_WLAN#) R398.1
N26607619: D16.C(CATHODE) R398.2
N26607860: P3.44(LED_WLAN#) R397.2
N26620998: P2.30(SMB_CLK) R415.2
N26621001: P2.32(SMB_DATA) R416.2
N26621044: P3.30(SMB_CLK) R418.2
N26621047: P3.32(SMB_DATA) R417.2
N26623594: TP55.1(PIN1) U21.D14(GPIO2_13/IFC_PAR0)
N26623597: TP56.1(PIN1) U21.D13(GPIO2_14/IFC_PAR1)
N26623758: R432.2 U21.W5(EC2_GTX_CLK/GPIO3_00/TSEC_1588_)
N26628373: R431.2 U21.L4(IRQ4/SDHC_CLK_SYNC_IN/GPIO1_24)
N26669713: C638.1 U45.21(INTVCC)
N26669717: C633.2 L30.1 U45.15(SW1) U45.16(SW2) U45.17(SW3) U45.18(SW4) U45.19(SW5)
N26669739: C633.1 U45.20(BST)
N26669755: C632.2 J25.1(A1) J25.3(A2) J25.5(A3) J25.7(A4) R434.2 U45.24(FB)
N26669803: R435.1 U45.3(RT)
N26669831: R436.1 R437.2 U45.4(EN/UV)
N26669847: C631.1 U45.2(TR/SS)
N26670020: TP58.1(PIN1) U45.23(PG)
N26671814: J25.8(B4) R433.1
N26671819: J25.6(B3) R439.1
N26671824: J25.4(B2) R441.1
N26671827: J25.2(B1) R440.1
N26682338: J19.2 R96.1
N26683109: J20.2 R36.1
N26683821: J23.2 R436.2
N26711184: C645.1 R447.2 U47.10(VIN+)
N26711194: C645.2 R446.2 U47.9(VIN-)
N26711585: R448.2 U47.1(A1)
N26711588: R449.2 U47.2(A0)
N26712218: R450.2 U42.1(A1)
N26712221: R451.2 U42.2(A0)
N26747830: J24.16 R452.2
N26747833: J24.15 R453.2
N26747836: J24.14 R454.2
N26747839: J24.13 R455.2
N26748165: J4.13 R456.2
N26748168: J4.14 R457.2
N26748171: J4.15 R458.2
N26748174: J4.16 R459.2
N26816813: Q29.1(BASE) R460.2
N26817083: Q30.1(BASE) R461.1
N26884619: R466.1 U48.3(R\E\S\E\T\)
N26901042: C657.1 U49.21(INTVCC)
N26901046: C652.2 L31.1 U49.15(SW1) U49.16(SW2) U49.17(SW3) U49.18(SW4) U49.19(SW5)
N26901068: C652.1 U49.20(BST)
N26901080: C651.2 J27.1(A1) J27.3(A2) J27.5(A3) J27.7(A4) R469.2 U49.24(FB)
N26901130: R470.1 U49.3(RT)
N26901158: R471.1 R472.2 U49.4(EN/UV)
N26901172: C650.1 U49.2(TR/SS)
N26901338: TP62.1(PIN1) U49.23(PG)
N26901371: J26.2 R471.2
N26901409: J27.8(B4) R473.1
N26901413: J27.6(B3) R476.1
N26901417: J27.4(B2) R475.1
N26901419: J27.2(B1) R474.1

Pads without a net: D24 2; D25 2; J1 3; J5 13 14 15 16; J13 2 5 8 10 14; P1 2 7; P2 3 5 8 10 12 14 16 17 19 20 36 37 38 42 43 46; P3 3 5 8 10 12 14 16 17 19 20 36 37 38 42 43 46; SW2 7 10; T1 2 5; T2 4 7 8 9; U1 4 7 8 25 28 31; U4 4 5 6 7; U5 33 38 39 40 41 42 43; U6 16 17 18 19 20 21 26 33 42 43 44; U7 12; U8 A11 A12 A13 A14 A15 A16 A17 B1 B10 B11 B13 B15 B17 B18 C1 C10 C12 C14 C16 C18 D1 D2 D10 D11 D13 D15 D17 E2 E12 E14 E16 F3 F4 F7 F9 F11 F13 F14 F15 F16 G3 G4 G6 G8 G10 G12 G14 G15 G16 H1 H2 H5 H7 H9 H11 H13 H14 H15 J1 J2 J14 J17 K2 K3 K17 L2 L3 L5 L17 M1 M2 M3 M4 M5 M14 M17 M18 N3 N4 N14 N15 N16 N18 P1 P2 P14 P15 P16 R15 R16 R17 R18 T1 T2 T14 T16 T17 T18 U2 U3 U7 U8 U10 U12 U13 U14 U15 U17 V1 V2 V3 V7 V8 V10 V12 V13 V14 V15 V17 V18; U9 8 23 24; U11 1 2 5 6 11 13 15 16; U12 1 2 5 6 11 13 15 16; U14 4 5 6 11 12 13; U16 A1 A2 A9 A10 B1 B9 B10 D6 D7 D8 E3 E4 E5 E6 E7 E8 F3 F4 F5 F6 F8 G3 G5 G6 G7 G8 H3 H5 H6 H7 J3 J5 L1 L2 L9 L10 M1 M2 M9 M10; U19 1 2; U20 27 28 30 53; U21 A16 AA22 AA23 AB23 AC19 F1 F2 F5 G3 G4 G5 K6 L6 M6 N6 N22 P6 P23 R6 R23 T5 T6 U6 U7 V17; U26 1 2 5 6 11 13 15 16; U33 9 10 11 12 13 14; U34 A3 G9 N7; U35 A3 G9 N7; U36 A3 G9 N7; U37 A3 G9 N7; U38 2 6 16 33 42 44 45 46; U39 A1 A2 A6 A7 A8 A9 A10 A11 A12 A13 A14 B1 B3 B4 B5 B6 B7 B8 B9 B10 B11 B12 B13 B14 C1 C3 C5 C7 C8 C9 C10 C11 C12 C13 C14 D1 D2 D3 D4 D12 D13 D14 E1 E2 E3 E5 E8 E9 E10 E12 E13 E14 F1 F2 F3 F10 F12 F13 F14 G1 G2 G3 G10 G12 G13 G14 H1 H2 H3 H5 H12 H13 H14 J1 J2 J3 J5 J12 J13 J14 K1 K2 K3 K6 K7 K10 K12 K13 K14 L1 L2 L3 L12 L13 L14 M1 M2 M3 M7 M8 M9 M10 M11 M12 M13 M14 N1 N3 N6 N7 N8 N9 N10 N11 N12 N13 N14 P1 P2 P7 P8 P9 P10 P11 P12 P13 P14; U40 4 6; U42 3; U43 5 6 7; U44 5 14 15; U47 3; U48 7 9 10 11 12 13

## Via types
v1: diameter 0.508, hole 0.254, TOP to BOTTOM, 2042 vias
v2: diameter 0.457, hole 0.203, TOP to BOTTOM, 711 vias
v3: diameter 1.016, hole 0.508, TOP to BOTTOM, 516 vias

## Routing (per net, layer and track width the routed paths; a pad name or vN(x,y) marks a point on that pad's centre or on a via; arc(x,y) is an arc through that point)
1V2_RST_N: length 280.9
  TOP w0.127: U37.L1 157.86,18.9 v2(158.26,18.5) ; v2(144.29,18.5) 143.89,18.9 U36.L1 ; v2(130.32,18.5) 129.92,18.9 U35.L1 ; U34.L1 115.95,18.9 v2(116.35,18.5)
  L3_INT1 w0.127: v1(205.67,142.42) 205.67,142.16 203.38,139.88 203.38,96.95 210.11,90.22 210.11,63.93 208.97,62.79 208.97,37.01 205.54,33.58 205.54,24.56 205.03,24.05 178.36,24.05 175.7,21.38 174.17,21.38 173.54,20.75 171.25,20.75 170.62,20.11 168.33,20.11 167.95,19.73 166.55,19.73 164.9,18.08 163.63,18.08 163.46,18.26 163.46,18.66 163.23,18.9 162.89,18.9 162.57,19.23 159.95,19.23 159.64,18.92 158.68,18.92 v2(158.26,18.5)
  L4_INT2 w0.127: v1(158.17,141.78) 166.81,141.78 171.76,146.73 201.35,146.73 v1(205.67,142.42)
  BOTTOM w0.127: v2(116.35,18.5) 116.42,18.5 116.83,18.9 119.54,18.9 120.43,19.78 123.76,19.78 124.64,18.9 127.89,18.9 128.78,18.01 129.83,18.01 v2(130.32,18.5) 130.72,18.9 133.67,18.9 134.5,19.73 137.17,19.73 138,18.9 141.68,18.9 142.55,18.03 143.82,18.03 v2(144.29,18.5) 144.69,18.9 147.76,18.9 148.57,19.71 151.34,19.71 152.15,18.9
  BOTTOM w0.152: Q15.3 206.69,143.43 v1(205.67,142.42) ; v2(158.26,18.5) 158.26,18.2 158.04,17.98 157.05,17.98 156.14,18.9 152.15,18.9 ; v1(158.17,141.78) R201.1 R200.2
1V8_RST_N: length 87.5
  TOP w0.152: v1(199.32,71.94) U20.14 ; U14.3 v1(197.67,102.66)
  L3_INT1 w0.127: v1(197.67,102.66) 202.75,107.74 202.75,140.38 205.54,143.18 211.38,143.18 v1(211.77,142.8)
  BOTTOM w0.152: v1(199.32,71.94) 200.08,72.7 200.08,96.57 197.67,98.98 v1(197.67,102.66) ; v1(211.77,142.8) 211.89,142.92 R197.2 Q14.3
12V: length 94
  TOP w0.254: 189.5,133.95 U7.8
  TOP w0.305: R446.1 82.35,87.42 83.37,86.41 97.47,86.41 100.89,89.84 100.89,93.34 101.33,93.77 R100.2
  TOP w0.508: R146.1 106.48,48.44 106.1,48.82 105.34,48.82
  TOP w0.635: 10.89,93.39 J23.1 ; J23.1 12.59,93.39 ; J23.1 11.74,92.54 ; 24.86,93.39 J26.1 ; J26.1 26.56,93.39 ; J26.1 25.71,92.54
  L4_INT2 w0.381: J23.1 12.59,93.39 ; J23.1 11.74,92.54 ; J23.1 10.89,93.39 ; J26.1 26.56,93.39 ; J26.1 25.71,92.54 ; J26.1 24.86,93.39
  L4_INT2 w0.508: J18.3 92.89,44.5
  BOTTOM w0.508: 181.16,105.97 181.16,95.17 180.27,94.28 R241.1 177.73,94.79 177.22,95.3 173.79,95.3 173.28,94.79 R242.1 ; 200.21,113.22 C282.1 ; C282.1 199.59,113.84 ; C282.1 200.83,113.84 ; 143.06,97.71 143.06,102.54 J9.2 ; v1(98.48,54.91) v1(98.48,54.02) ; v1(86.04,63.55) 86.54,63.04 C408.2
  BOTTOM w0.762: 190.05,126.67 190.18,126.54 191.32,127.68 204.78,127.68 205.92,126.54 J21.3 J20.3
  vias: v1(9.71,90.09) v1(9.71,88.95) v1(10.72,90.09) v1(10.72,88.95) v1(30.54,81.71) v1(30.54,80.69) v1(31.68,81.71) v1(31.68,80.69) v1(82.1,63.55) v1(82.1,62.79) v1(84,63.55) v1(84,62.66) v1(98.48,53.01) v1(98.48,51.99) v1(103.82,96.7) v1(103.82,95.43) v1(103.82,94.16) v1(103.82,92.89) v1(104.45,48.82) v1(105.09,50.59) v1(105.09,49.58) v1(105.09,47.93) v1(105.21,96.7) v1(105.21,95.43) v1(105.21,94.16) v1(105.21,92.89) v1(187.38,130.1) v1(188.14,131.87) v1(188.14,130.99) v1(188.14,130.1) v1(193.6,112.06) v1(194.75,112.06) v1(195.89,112.06) v1(197.03,112.06) v1(198.05,112.06) v1(199.19,112.06) v1(200.46,112.06)
12V_DECT: length 323
  TOP w0.508: R247.1 v1(77.78,58.6) ; R232.2 v1(65.97,95.04) ; R231.1 v1(73.84,94.41) ; D9.A v1(83.24,92.76)
  L3_INT1 w0.508: J23.3 J26.3 ; v1(65.97,95.04) 73.21,95.04 v1(73.84,94.41) 73.84,103.17 v1(76.26,105.59)
  L4_INT2 w0.508: 63.88,145.71 F1.2 ; F1.2 62.62,146.97 ; F1.2 63.88,148.22 ; F1.2 65.14,146.97 ; J21.1 209.99,124.76 210.5,124.25 210.5,113.46 205.8,108.76 180.14,108.76 178.75,107.36 147.12,107.36 146.36,106.6 136.58,106.6 134.55,104.57 J19.1
  BOTTOM w0.508: v1(83.24,92.76) 81.59,94.41 v1(73.84,94.41) 73.84,92.76 74.73,91.87 74.73,84.12 76.51,82.34 76.51,62.53 77.78,61.26 v1(77.78,58.6) 77.78,57.07 79.94,54.91 79.94,49.58 89.97,39.55 J18.1 ; v1(65.97,95.04) 63.81,97.2 26.98,97.2 J26.3 ; J21.1 J20.1 ; J19.1 134.55,100.38 134.04,100.89 82.48,100.89 v1(77.78,105.59)
  vias: v1(76.13,107.49) v1(76.26,108.76) v1(76.38,110.03) v1(77.78,110.03) v1(77.78,108.76) v1(77.78,107.36)
12V_SUP: length 17.6
  TOP w0.508: R236.2 74.61,102.54 78.54,98.6 R97.2 78.54,95.45 D10.C D9.C
AVDD_CGA1: length 180
  TOP w0.254: U48.16 156.79,104.94 C647.1 ; v1(176.84,54.83) U25.42 ; v1(179.76,60.33) U25.31 ; v1(99.43,12.68) 98.93,12.68 97.59,14.02 95.81,14.02 95.28,14.55 U38.25 ; v1(184.33,60.33) U25.18 ; v1(184.33,54.83) U25.7
  TOP w0.305: U21.H14 144.2,62.41 v2(144.6,62.01) ; U21.H15 144.2,61.61 v2(144.6,61.21) ; U21.H12 144.2,64.01 v2(144.6,64.41) ; U21.T8 v2(137.4,67.61) ; U21.H11 v2(144.6,65.21) ; U21.L8 v2(142.2,67.61) ; U21.H13 144.2,63.21 v2(144.6,62.81) ; U16.G4 191.43,87.86 v2(191.03,88.26) ; U21.P8 v2(138.99,67.61) ; U16.D3 v2(194.23,89.06) ; U21.R8 v2(138.19,67.61) ; U16.H8 v2(190.23,84.26) ; U21.J8 v2(143.8,67.61) ; U16.J6 v2(190.23,85.86) ; v1(179.74,78.93) U20.29
  TOP w0.508: R16.1 v1(209.35,144.7) ; R150.1 v1(177.73,39.8) ; U14.14 v1(197.67,96.44) ; R17.1 v1(213.92,142.8) ; R142.1 v1(176.21,49.58) ; R155.2 v1(189.54,35.48) ; R154.1 v1(210.24,36.5) ; v1(198.94,54.91) 198.88,54.85 U27.5 ; v1(173.79,99.24) 167.57,99.24 161.85,104.95 C647.1 ; U24.5 v1(198.94,58.79) ; R156.2 v1(191.19,35.48) ; R165.1 205.16,21.13 205.92,21.89 205.92,24.56 v1(206.94,25.58) ; R153.1 v1(206.3,36.5) ; R163.1 v1(209.35,27.48) ; R144.2 v1(180.02,49.58) ; U23.5 v1(198.94,62.72) ; R461.2 v1(205.03,26.21) ; R143.2 v1(177.98,49.58) ; R460.1 v1(205.03,28.12)
  L3_INT1 w0.508: v1(198.94,54.91) v1(198.94,58.79) v1(198.94,62.72)
  L5_PWR w0.127: J11.1 186.11,95.99 ; J11.1 187.18,94.92 ; J11.1 186.11,93.85 ; J11.1 185.04,94.92 ; J10.2 187.18,98.6 ; J10.2 186.11,99.67 ; J10.2 185.04,98.6 ; J10.2 186.11,97.53
  BOTTOM w0.254: v1(176.84,54.83) 176.63,55.04 C461.1 ; v1(191.57,49.71) 191.86,49.42 U44.13 ; v1(184.33,54.83) 184.51,54.66 C466.1
  BOTTOM w0.305: C310.1 154.91,79.84 C311.1 ; R243.2 194.24,89.08 v2(194.23,89.06) ; C297.1 143.86,84.29 143.69,84.12 143.06,84.12 ; R290.2 164.9,62.91 165.16,63.17
  BOTTOM w0.381: R301.2 198.43,74.09 v1(199.45,75.11) ; v1(179.74,78.93) 179.47,78.66 C317.1 ; R420.2 122.99,77.9 122.48,78.41 v1(121.98,78.41) 121.6,78.41 121.21,78.03 R422.2 ; R421.2 v1(128.71,82.34) ; v1(128.83,75.74) 129.09,75.99 R289.1 ; C290.1 190.98,88.31 v2(191.03,88.26) ; v1(99.43,12.68) 99.75,12.37 99.75,9.07 v1(101.02,7.8) ; R424.1 124.77,78.03 124.39,78.41 v1(123.88,78.41)
  BOTTOM w0.508: v1(135.44,80.44) 135.57,80.31 R277.2 ; R302.2 165.28,73.07 ; R245.1 v1(206.69,87.42) ; R276.1 v1(206.69,78.53) ; v1(140.14,83.61) C299.1 142.17,83.61 142.68,84.12 143.06,84.12 ; v1(142.42,79.8) 142.8,79.42 R274.1 ; R281.1 132.26,75.87 v1(132.26,76.95) ; v1(152.96,77.9) C312.1 153.85,79.3 154.36,79.8 C310.1 ; R328.1 v1(160.46,57.96) ; R467.2 196.97,62.72 v1(198.94,62.72) 201.92,62.72 206.05,58.6 R135.1 R138.1 R140.1 ; R273.1 v1(147.25,80.19) ; R262.1 v1(206.69,81.07) ; R253.1 v1(206.69,84.88) ; v1(209.35,144.7) 209.99,144.07 R197.1 ; C301.1 190.23,83.67 v2(190.23,84.26) ; R304.2 165.41,72.06 ; R331.1 v1(160.33,53.64) ; v2(190.23,85.86) 190.6,85.86 C296.1 ; R308.2 165.54,71.04 ; R292.2 165.28,75.11 ; R314.2 165.41,67.99 ; R356.1 v1(175.19,49.58) ; v1(184.33,60.33) 184.54,60.12 C444.1 ; R238.2 v1(192.59,99.74) ; R468.2 v1(160.97,56.56) ; R317.2 165.28,66.98 ; R325.2 v1(160.46,61.9) ; R299.2 165.28,74.09 ; R324.1 165.41,63.93 ; R255.1 v1(206.69,83.61) ; R251.1 v1(206.69,86.15) ; 174.55,97.58 v1(174.55,99.24) ; R279.1 v1(131.88,80.44) ; R367.1 v1(178.82,38.4) ; R193.1 v1(209.35,149.91) ; L29.2 158.74,63.62 v1(159.31,63.04) 160.08,63.04 R323.1 ; R283.1 165.54,76.5 ; R257.1 v1(206.69,82.34) ; R368.1 v1(177.48,38.4) ; R237.2 v1(200.21,99.87) ; R312.2 165.28,69.01 ; R194.2 v1(212.4,150.67) ; R272.1 v1(148.52,80.31) ; R319.2 165.28,65.96 ; C287.1 v1(197.67,96.44) ; R268.1 v1(206.69,79.8) ; R310.1 165.41,70.03 ; R321.1 165.41,64.95 ; R424.1 R423.1 ; R239.2 v1(191.32,98.98)
  vias: v1(103.56,7.8) v1(104.32,7.54) v1(104.58,8.3) v1(105.21,7.54) v1(105.59,8.3) v1(106.1,7.54) v1(106.48,8.05) v1(166.68,76.5) v1(166.68,75.49)
AVDD_SD1_PLL1: length 91.2
  TOP w0.305: U38.18 91.78,15.19 91.5,14.91 91.5,14.4 v1(91.24,14.15)
  TOP w0.508: v1(115.63,57.33) 115.5,57.2 v1(115.5,53.77)
  L3_INT1 w0.508: v1(91.24,14.15) 92.26,13.13 97.08,13.13 98.23,14.27 98.23,15.42 97.21,16.43 97.21,25.07 97.85,25.7 102.8,25.7 103.31,26.21 103.31,32.56 106.48,35.74 106.48,40.05 112.71,46.28 112.71,50.98 v1(115.5,53.77)
  BOTTOM w0.305: v1(91.24,14.15) 90.86,13.76 C590.1
  BOTTOM w0.508: FL2.3 115.59,57.36 v1(115.63,57.33) 115.37,57.07 R329.2 ; R294.2 113.21,71.17 114.61,69.77 114.61,64.69 113.59,63.68 113.59,55.17 114.99,53.77 v1(115.5,53.77) R330.2
GND: length 1461.5
  TOP w0.081: U39.N2 184.75,13.46 184.75,14.11 v2(184.46,14.4) 184.25,14.19 184.25,13.46 U39.N2
  TOP w0.254: v1(94.42,49.96) 94.16,50.22 U28.12 ; v1(94.42,49.96) 94.66,50.2 ; v1(94.42,49.96) 94.57,49.8 U28.9 ; U28.13 93.66,50.22 v1(93.4,49.96) 93.16,50.2 U28.14 ; v1(88.58,61.9) 88.84,61.64 U22.12 ; v1(88.58,61.9) 88.33,61.66 ; v1(88.58,61.9) 88.42,62.05 U22.9 ; U4.8 v1(190.94,145.08) ; U39.P4 v2(183.35,12.21) ; 88.33,61.66 88.23,61.55 U22.10 ; 88.33,61.66 U22.11 ; U25.4 184.39,53.33 v1(184.33,53.39) ; U38.48 94.28,24.17 94.42,24.31 94.42,24.56 94.67,24.81 v1(94.8,24.81) ; 90.86,21.64 90.83,21.61 U38.4 ; v1(184.33,61.77) 184.39,61.83 U25.21 ; U28.27 94.16,45.89 v1(94.42,46.15) 94.66,45.91 ; 94.66,50.2 94.76,50.3 U28.10 ; 94.66,50.2 U28.11 ; 94.66,45.91 U28.28 ; 94.66,45.91 94.76,45.8 U28.1 ; U25.15 184.35,58.83 v1(184.33,58.85) ; v1(99.37,17.96) 98.86,17.96 98.71,18.11 U38.32 ; v2(189.03,11.73) 189.51,12.2 U39.C4 ; v1(88.58,63.17) 88.65,63.09 88.65,62.73 88.47,62.55 U22.8 ; U39.K8 v2(186.62,10.21) ; U22.25 89.83,65.95 v1(89.59,65.71) 89.33,65.97 U22.26 ; U28.26 93.66,45.89 v1(93.4,46.15) 93.16,45.91 U28.25 ; v2(183.33,11.21) U39.P6 U39.N5 ; U39.G5 187.5,11.6 v2(187.13,11.22) ; U25.39 176.86,56.33 v1(176.84,56.31) ; v1(105.97,56.94) 106.07,57.04 U26.8 ; U22.27 88.84,65.97 v1(88.58,65.71) 88.33,65.95 ; U38.47 94.78,22.8 94.8,22.78 ; U47.7 v1(76.76,87.05) ; U39.H10 187.01,9.58 v2(187.13,9.71) ; U39.E7 188.27,10.71 v2(187.89,10.34) ; 88.33,65.95 88.23,66.05 U22.1 ; 88.33,65.95 U22.28 ; v1(176.84,53.33) U25.45 ; v1(184.21,51.83) U25.1 ; v1(179.76,61.52) 179.45,61.83 U25.28 ; v1(176.84,58.83) U25.34 ; v1(94.42,48.82) 94.91,49.3 U28.8 ; U25.10 184.61,56.33 184.33,56.06 v1(184.33,55.8) ; U42.7 v1(73.84,62.16) ; U22.13 89.33,61.64 v1(89.59,61.9) 89.83,61.66 U22.14 ; U38.5 90.84,21.11 90.86,21.13 ; v1(184.33,63.33) U25.24 ; U48.8 v1(161.34,98.35) ; U48.2 v1(157.44,95.43)
  TOP w0.279: 36.38,82.47 36.37,82.48 U49.13 36.37,83.99 v1(36.63,84.25) 36.87,84.01 U49.14 36.87,82.33 36.63,82.09 ; v1(35.62,85.27) 35.38,85.03 U49.8 ; v1(13.26,85.01) 13.55,85.29 U45.9 ; v1(13.26,85.01) 13.05,85.23 ; v1(13.26,85.01) 13.01,84.75 U45.12 11.37,84.75 11.36,84.76 ; 35.4,88.53 v1(35.62,88.31) 35.88,88.57 U49.27 ; 35.4,88.53 35.38,88.55 U49.28 ; 35.4,88.53 U49.1 ; 11.49,84.25 11.49,84.25 U45.13 13.01,84.25 v1(13.26,84) 13.02,83.75 U45.14 11.35,83.75 11.11,84 ; U45.1 17.55,84.85 17.52,84.82 ; 35.4,84.03 35.38,84.01 U49.11 35.38,82.46 35.49,82.34 ; 35.4,84.03 U49.10 ; 35.4,84.03 v1(35.62,84.25) ; v1(14.28,85.01) 14.05,85.25 U45.8 ; 13.05,85.23 U45.10 ; 13.05,85.23 13.02,85.25 U45.11 11.47,85.25 11.36,85.14 ; U45.25 17.57,83.75 v1(17.33,84) 17.59,84.25 U45.26 ; 17.52,84.82 v1(17.33,85.01) 17.57,85.25 U45.28 ; 17.52,84.82 17.59,84.75 U45.27 ; v1(35.62,84.25) 35.34,84.53 U49.9 ; v1(35.62,84.25) 35.88,83.99 U49.12 35.88,82.35 35.87,82.34 ; U49.25 36.87,88.55 v1(36.63,88.31) 36.37,88.57 U49.26
  TOP w0.305: U37.A8 v2(163.86,27.3) ; v2(115.55,16.9) 115.95,17.3 U34.N1 ; U21.M16 141,60.81 v2(141.4,60.41) ; U21.V16 136.2,60.81 v2(135.8,60.41) ; U34.D9 v2(122.75,24.9) ; U21.T14 137.8,62.41 v2(137.4,62.01) ; v2(115.55,19.3) 115.95,19.7 U34.K1 ; U36.E9 v2(150.69,24.1) ; v2(138.19,59.61) 138.6,60.01 U21.R17 ; U21.P22 139.4,56.01 v2(138.99,55.61) ; U21.P18 139.4,59.21 v2(138.99,58.81) ; C117.2 v1(153.22,31.29) ; U37.A2 v2(158.26,27.3) ; U21.P20 139.4,57.61 v2(138.99,57.21) ; C609.2 180.27,87.93 180.55,87.65 v1(180.55,86.64) ; U21.U15 137,61.61 v2(136.6,61.21) ; v2(138.99,62.01) 139.4,62.41 U21.P14 ; U37.A9 v2(164.66,27.3) ; U36.G1 v2(143.49,21.7) ; v2(145.4,58.81) 145,59.21 U21.G18 ; U21.A2 149.8,72.01 v2(150.2,72.41) ; U21.P2 v2(139.8,72.41) ; U21.Y17 134.6,60.01 v2(135,59.61) 135.4,60.01 U21.W17 ; v2(145.4,62.01) 145,61.61 U21.G15 ; U21.U13 137,63.21 v2(136.6,62.81) ; U36.K9 150.29,19.7 v2(150.69,19.3) ; U21.L16 141.8,60.81 v2(142.2,60.41) ; U21.J16 143.4,60.81 v2(143.8,60.41) ; v2(164.66,19.3) 164.26,19.7 U37.K9 ; U21.A18 v2(150.2,58.81) ; C123.2 v1(174.81,27.1) ; U37.N1 157.86,17.3 v2(157.46,16.9) ; U16.F7 192.23,85.46 v2(192.63,85.06) ; v2(144.6,60.41) 144.2,60.81 U21.H16 ; U21.AB6 v2(132.6,69.21) ; v2(146.2,72.41) 146.45,72.15 146.45,72.15 U21.E2 ; U21.AB1 v2(132.6,73.21) ; v2(137.4,60.41) 137.8,60.81 U21.T16 ; U21.L5 v2(142.2,70.01) ; U36.D1 v2(143.49,24.9) ; C128.2 v1(174.81,25.7) ; U21.W6 v2(135.8,69.21) U21.V6 ; U21.Y12 134.6,64.01 v2(135,64.41) 135.4,64.01 U21.W12 ; U21.G17 145,60.01 v2(145.4,59.61) ; v1(179.41,22.93) 178.11,22.93 ; v1(89.34,15.16) 89.97,15.16 90.28,15.47 U38.15 ; U35.K1 129.92,19.7 v2(129.52,19.3) ; U35.E9 v2(136.72,24.1) ; U21.N17 140.2,60.01 v2(139.8,59.61) ; U21.G12 v2(145.4,64.41) U21.G11 ; C81.2 v1(170.87,96.19) ; U38.14 89.56,16.27 89.21,15.92 v1(88.83,15.92) ; v2(164.66,21.7) 164.26,21.3 U37.H9 ; v2(142.2,62.81) 141.8,63.21 U21.L13 ; U21.G10 v2(145.4,66.01) U21.G9 ; U36.A8 v2(149.89,27.3) ; U36.H9 150.29,21.3 v2(150.69,21.7) ; U9.10 205.42,115.61 v1(205.67,115.36) ; v2(143.49,16.9) 143.89,17.3 U36.N1 ; U34.G1 v2(115.55,21.7) ; U21.K17 142.6,60.01 v2(143,60.41) 142.6,60.81 U21.K16 ; U21.T22 137.8,56.01 v2(137.4,55.61) 137,55.21 U21.U23 ; U21.G14 145,62.41 v2(145.4,62.81) 145,63.21 U21.G13 ; U34.H9 122.35,21.3 v2(122.75,21.7) ; U21.P12 139.4,64.01 v2(138.99,64.41) ; U21.U5 v2(136.6,70.01) ; U21.N13 140.2,63.21 v2(139.8,62.81) ; U21.E9 v2(147,66.81) ; v2(142.2,58.81) 141.8,59.21 U21.L18 ; U21.N7 v2(139.8,68.41) ; U21.F20 145.8,57.61 v2(146.2,57.21) ; U21.V7 v2(135.8,68.41) ; U35.K9 136.32,19.7 v2(136.72,19.3) ; v2(141.4,58.81) 141,59.21 U21.M18 ; U34.C8 v2(121.95,25.7) ; v2(136.6,60.41) 137,60.81 U21.U16 ; U21.J19 143.4,58.41 v2(143,58.81) 142.6,59.21 U21.K18 ; v2(143,57.21) 142.6,57.61 U21.K20 ; U34.E1 v2(115.55,24.1) ; U21.E19 146.6,58.41 v2(147,58.01) ; U36.C8 v2(149.89,25.7) ; U21.T7 v2(137.4,68.41) ; U21.D20 v2(147.8,57.21) ; U21.AB10 v2(132.6,66.01) U21.AC10 ; U21.AA6 v2(133.4,68.41) U21.AA7 ; U36.A2 v2(144.29,27.3) ; U21.P7 v2(138.99,68.41) ; v2(150.04,55.17) 150.04,55.76 U21.A22 ; U21.B13 149,63.21 149,63.21 v2(148.6,62.81) ; U21.U2 v2(136.6,72.41) ; U21.AA12 v2(134.2,64.41) U21.AA11 ; U35.A9 v2(136.72,27.3) ; U21.J11 v2(143.8,65.21) ; v2(131.8,59.61) 132.2,60.01 U21.AC17 ; U21.E22 146.77,55.84 146.77,55.84 v2(147,55.61) ; U16.C5 v2(195.03,87.46) ; U21.AB12 v2(133.4,64.41) ; U21.B1 149,72.81 v2(149.4,73.21) ; v1(205.67,113.59) 205.92,113.34 U9.22 ; U21.AA16 133.8,60.81 v2(133.4,61.21) 133.8,61.61 U21.AA15 ; v1(135.57,107.74) 135.84,107.47 U11.10 ; v2(147.8,58.81) 147.4,59.21 147.39,59.21 U21.D18 ; U21.AA10 v2(133.4,66.01) U21.AA9 ; U21.R5 v2(138.19,70.01) ; U21.AC8 131.52,67.21 v2(131.37,67.36) ; U21.J22 143.4,56.01 v2(143.8,55.61) ; U21.B7 149,68.01 v2(149.4,68.41) ; U21.D3 v2(147.8,71.61) ; v2(149.4,61.21) 149,60.81 U21.B16 ; U21.N16 140.2,60.81 v2(139.8,60.41) ; U21.N9 v2(139.8,66.81) ; U21.R16 138.6,60.81 v2(138.19,60.41) ; U21.E1 v2(146.2,73.21) ; U21.G2 v2(145.4,72.41) ; v1(103.43,56.94) 103.03,56.54 U26.10 ; U21.B10 149,65.61 v2(149.4,66.01) ; U36.E1 v2(143.49,24.1) ; U21.Y10 v2(135,66.01) U21.W10 ; v2(143.8,62.81) 143.4,63.21 U21.J13 ; v2(143.8,58.01) 144.2,57.61 U21.H20 ; C112.2 v1(166.73,32.18) ; v2(140.6,56.41) 141,56.81 U21.M21 ; U37.D1 v2(157.46,24.9) ; U21.AC15 132.2,61.61 v2(132.6,61.21) 133,61.61 U21.AB15 ; U37.E9 v2(164.66,24.1) ; U21.L22 141.8,56.01 v2(142.2,55.61) ; v2(122.75,19.3) 122.35,19.7 U34.K9 ; v1(135.57,110.16) 135.34,110.38 U11.8 ; U21.AB4 v2(132.6,70.81) ; U21.L11 v2(142.2,65.21) ; U37.G1 v2(157.46,21.7) ; U21.AB8 v2(133.4,67.61) U21.AA8 ; U35.D9 v2(136.72,24.9) ; U21.B20 v2(148.6,58.01) U21.C19 ; U16.K3 v2(189.43,89.06) ; U21.AA14 133.8,62.41 v2(133.4,62.81) 133.8,63.21 U21.AA13 ; U21.B18 v2(149.4,58.81) ; U21.V4 v2(135.8,70.81) ; v2(146.2,61.21) 146.59,61.61 146.6,61.61 U21.E15 ; U37.C8 v2(163.86,25.7) ; v1(142.17,107.74) 142.44,107.47 U12.10 ; U21.L2 v2(142.2,72.41) ; U36.K1 143.89,19.7 v2(143.49,19.3) ; U21.F17 145.8,60.01 v2(146.2,59.61) ; U21.C22 v2(148.6,55.61) ; U35.A8 v2(135.92,27.3) ; U21.C2 148.19,72.01 v2(148.6,72.41) ; U35.H9 136.32,21.3 v2(136.72,21.7) ; U21.E6 v2(147,69.21) ; U21.J5 v2(143.8,70.01) ; U21.C4 148.19,70.41 v2(148.6,70.81) ; U21.AC6 v2(131.8,69.21) ; v2(139.8,58.81) 140.2,59.21 U21.N18 ; U21.K7 v2(143,68.41) U21.J7 ; U35.N1 129.92,17.3 v2(129.52,16.9) ; U36.A9 v2(150.69,27.3) ; v2(141.4,62.01) 141,62.41 U21.M14 ; U20.33 179.56,76.93 v1(179.76,77.14) ; U21.H7 v2(144.6,68.41) ; v1(177.09,67.43) U20.52 ; U21.Y2 v2(134.2,72.41) ; v2(143,62.01) 142.6,62.41 U21.K14 ; v2(149.4,71.61) 149,71.21 U21.B3 ; U21.U8 v2(136.6,67.61) ; U37.K1 157.86,19.7 v2(157.46,19.3) ; U21.P16 139.4,60.81 v2(138.99,60.41) ; U21.R9 v2(138.19,66.81) ; U21.G22 145,56.01 v2(145.4,55.61) ; U21.Y8 v2(134.2,67.61) ; U34.A2 v2(116.35,27.3) ; C82.2 v1(170.49,95.43) ; U21.W8 v2(135,67.61) ; U34.A8 v2(121.95,27.3) ; U34.D1 v2(115.55,24.9) ; U21.C1 148.19,72.81 v2(148.6,73.21) ; U37.E1 v2(157.46,24.1) ; v1(142.17,110.16) 141.94,110.38 U12.8 ; U21.J9 v2(143.8,66.81) ; U21.AC2 v2(131.8,72.41) ; U21.L9 v2(142.2,66.81) ; U21.Y6 v2(135,69.21) ; v1(189.77,22.93) U33.15 ; v2(143,66.01) U21.K10 ; U21.R11 v2(138.19,65.21) ; v2(146.2,71.61) U21.F3 v2(145.4,71.61) ; U16.K8 v2(188.63,84.26) ; U21.Y15 134.6,61.61 v2(135,61.21) 135.4,61.61 U21.W15 ; U21.T10 v2(137.4,66.01) ; U21.M7 v2(141.4,68.41) ; v2(143,64.41) U21.K12 ; U21.G1 v2(145.4,73.21) ; U21.G6 v2(145.4,69.21) ; U35.E1 v2(129.52,24.1) ; C114.2 120.33,31.8 v1(120.2,31.93) ; U21.M12 v2(141.4,64.41) ; U21.V9 v2(135.8,66.81) ; v2(144.6,59.61) 144.2,60.01 U21.H17 ; U21.Y5 v2(134.2,70.01) ; v2(141.4,66.01) U21.M10 ; v2(132.6,59.61) U21.AB17 133,60.01 133.39,60.39 133.77,60.01 U21.AA17 ; v2(145.4,58.01) 145,58.41 U21.G19 ; v1(182.82,26.84) U32.8 ; U35.G1 v2(129.52,21.7) ; U36.D9 v2(150.69,24.9) ; v2(147,64.41) U21.E12 ; U21.L7 v2(142.2,68.41) ; U35.C8 v2(135.92,25.7) ; U21.U11 v2(136.6,65.21) ; U37.D9 v2(164.66,24.9) ; U43.16 59,79.05 58.86,78.92 C469.2 ; U34.A9 v2(122.75,27.3) ; U21.H2 v2(144.6,72.41) ; U21.N11 v2(139.8,65.21) ; U34.E9 v2(122.75,24.1) ; v2(138.19,62.81) 138.6,63.21 U21.R13 ; U21.U9 v2(136.6,66.81) ; U21.U12 v2(136.6,64.41) ; U21.R7 v2(138.19,68.41) ; U35.D1 v2(129.52,24.9) ; U21.P10 v2(138.99,66.01) ; U21.AC12 v2(131.8,64.41) ; U35.A2 v2(130.32,27.3)
  TOP w0.381: U8.D5 154.43,134.58 154,134.14 v1(153.94,134.09) 153.44,133.58 U8.E4 ; U8.B9 v1(158.93,136.08) ; U8.D7 156.43,134.58 v1(155.95,134.1) U8.E6 ; v1(114.36,110.41) 114.16,110.61 U13.7 114.16,113.77 C286.2 ; v1(193.23,26.84) U33.8 ; U8.C11 v1(160.93,135.08) U8.D12 ; v1(149.93,137.07) 150.43,137.58 U8.A1 ; U8.N1 v1(150.93,125.08) ; U8.R9 v1(157.94,123.09) ; U8.B7 v1(156.93,136.08) U8.C8 ; C111.2 v1(165.03,32.81) ; v1(183.79,117.65) 183.79,116.76 183.41,116.38 C55.2 182.81,116.38 182.54,116.65 v1(182.54,117.64) ; U8.C15 v1(164.93,135.08) ; U8.F6 v1(154.99,132.14) ; U8.J13 v1(161.93,130.08) U8.H12 ; U8.P18 v1(167.93,124.08) ; U13.3 114.81,107.43 v1(115.12,107.74) 115.46,107.4 U13.4 ; U10.4 109.24,109.35 v1(109.53,109.65) ; U8.T5 v1(153.93,123.08) U8.R4 ; U8.N11 v1(160.93,125.09) ; U8.M10 v1(158.93,127.08) U8.L9 ; U8.R2 v1(150.95,123.1) ; C139.2 v1(189.03,20.37) ; v1(160.93,121.08) 160.68,121.33 160.68,121.33 U8.U11 ; U8.T9 v1(157.93,122.08) ; U8.V16 v1(165.93,120.08) ; v1(175.82,150.16) 175.6,149.93 U2.15 ; U8.U9 v1(157.99,121.14) ; U8.G11 v1(159.93,132.08) U8.F10 ; U13.1 113.51,107.4 v1(113.85,107.74) 114.16,107.43 U13.2 ; U8.B3 v1(152.93,136.08) U8.C4 ; U8.T7 v1(156.93,123.08) 156.43,123.58 U8.R7 ; U8.A18 167.44,137.58 v1(167.93,137.08) ; C149.2 v1(176.71,13) ; U8.K6 v1(154.97,129.05) 154.44,129.58 U8.J5 ; U8.E13 v1(162.93,133.08) ; v1(183.7,125.52) 183.7,124.27 183.43,124 C47.2 182.68,124 182.3,124.38 v1(182.3,125.52) ; U8.D9 158.44,134.58 v1(158.93,134.08) ; C628.2 v1(60.51,148) ; U8.G7 v1(156.9,131.11) U8.H8 ; U8.B5 v1(154.93,136.08) U8.C6 ; U8.J11 v1(159.93,130.08) U8.H10 ; U8.N13 v1(161.93,126.09) U8.M12 ; U8.M8 v1(156.93,127.08) U8.L7 ; U8.H6 v1(154.93,131.08) U8.G5 ; U8.K10 v1(158.93,129.08) U8.J9 ; U8.F8 v1(157.9,132.11) 158.43,131.58 U8.G9 ; U8.L13 v1(161.94,127.09) ; R63.1 v1(114.86,127.81) ; U8.C17 v1(165.93,135.07) ; U8.D3 v1(151.93,135.08) U8.C2 ; U8.P8 v1(156.93,125.08) U8.N7 ; U8.J7 v1(156.93,129.08) U8.K8 ; U8.P6 v1(154.93,124.08) U8.R6 ; U8.T3 v1(152.9,123.05) ; U31.9 v1(192.33,28.37) ; v1(120.2,31.93) C110.2 ; U8.U18 v1(167.93,121.08) ; U8.R14 v1(163.94,123.08) ; C115.2 v1(155,32.31) ; U8.U16 v1(165.93,121.08) ; U8.D18 167.44,134.58 v1(167.93,135.07) ; U8.R13 v1(162.93,123.08) U8.T13 ; U8.B16 v1(165.93,136.08) ; U8.T15 v1(164.9,123.05) ; v1(154.93,120.08) 154.43,120.58 U8.V5 ; U8.T11 v1(160.93,122.08) ; U8.D16 v1(164.93,134.07) ; C163.1 v1(176.71,7.8) ; C152.2 v1(176.71,10.72) ; U8.E11 160.44,133.58 v1(160.94,133.07) U8.F12 ; U8.U5 v1(154.93,121.08) ; U8.V11 160.72,120.3 160.72,120.3 v1(160.93,120.08) ; U8.B12 v1(161.93,136.08) U8.C13 ; C66.2 v1(106.74,117.02) ; U8.D14 163.44,134.58 v1(163.94,134.08) ; v1(157.92,120.06) 158.43,120.58 U8.V9 ; U8.L4 v1(152.96,128.06) ; C138.2 v1(187.76,20.37) ; C157.2 v1(176.71,9.07) ; U8.P12 v1(161.93,124.08) ; C627.2 v1(59.11,148) ; U8.N5 v1(154.94,126.09) U8.M6 ; U8.P17 v1(166.93,124.08) ; U8.K12 v1(160.93,129.08) ; U8.N9 v1(158.9,125.11) 159.21,124.81 159.21,124.81 U8.P10 ; U8.H4 153.45,130.58 v1(153.95,131.08) ; U8.U1 v1(150.93,121.08) ; U8.P3 v1(151.93,125.08) U8.N2 ; C156.2 v1(160.97,8.18) ; U8.R1 v1(149.88,123.02) ; U8.B14 v1(163.94,136.08) ; v1(165.94,134.07) U8.E17 ; U8.L11 v1(160.93,127.08) ; U8.E1 v1(149.89,134.13) ; U8.R11 v1(160.93,123.08) ; U8.E15 v1(164.93,133.08)
  TOP w0.508: C130.2 84.72,26.13 ; C130.2 84.72,24 ; C130.2 85.46,25.07 ; C86.2 91.17,79.8 v1(90.7,80.27) ; R122.2 v1(107.88,75.61) ; 41.97,75.66 C658.2 ; C658.2 41.97,79.12 ; C658.2 40.77,77.39 ; C477.2 v1(57.08,82.09) ; 84.72,26.67 C122.2 ; C122.2 84.72,28.8 ; C122.2 85.46,27.73 ; 108.83,16.89 C143.2 108.83,19.02 ; v1(142.17,130.48) 143.31,130.48 143.69,130.1 C35.2 143.69,128.83 143.34,128.47 v1(142.27,128.47) ; C162.2 v1(171.63,7.03) ; R29.1 v1(197.8,137.46) ; C657.2 v1(43.36,86.41) ; v1(194.24,152.96) L2.1 v1(195.26,154.04) ; C155.2 107.42,11.43 ; C155.2 105.29,11.43 ; C155.2 106.36,12.18 ; R136.2 v1(214.31,56.44) ; C135.2 v1(174.68,20.62) ; C18.2 v1(145.09,138.22) ; R114.2 v1(107.64,79.55) ; C653.2 52.56,80.57 ; C653.2 51.36,82.29 ; C653.2 51.36,78.84 ; R51.1 v1(117.28,131.37) ; v1(99.88,65.83) 100.29,66.25 C90.2 ; C79.2 v1(101.78,101.78) ; C79.2 v1(101.78,96.82) 101.53,96.57 C80.2 ; C79.2 102.93,99.36 v1(103.31,99.74) ; R90.2 v1(211.77,111.17) ; v1(71.18,82.98) 70.54,83.61 R355.2 ; R131.1 v1(214.18,61.26) ; v1(86,81.87) Y5.4 ; C77.2 88.04,90.82 ; C77.2 88.04,88.61 ; C77.2 85.98,89.71 ; C44.2 169.86,129.33 v1(169.6,129.59) ; 108.83,23.59 C133.2 108.83,21.46 ; C624.2 v1(20.5,68.37) ; C19.1 194.37,137.72 v1(194.62,137.46) ; R141.2 v1(214.31,53.13) ; C124.2 v1(92.51,27.48) ; P2.9 v1(45.15,62.28) ; C99.2 v1(93.91,52.63) ; P3.35 v1(54.33,138.78) ; R476.2 v1(31.3,94.66) ; v1(30.99,62.02) 31.55,62.58 P2.35 ; C649.2 50.86,90.33 ; C649.2 50.86,88.58 ; C649.2 51.61,89.46 ; v1(138.11,129.08) 138.34,129.31 138.34,130.37 137.98,130.73 C34.2 137.22,130.1 v1(137.22,129.08) ; R60.1 v1(190.18,128.83) ; R72.1 R73.1 99.75,124.25 v1(99.37,123.87) ; P2.40 v1(29.55,53.93) ; R129.2 84.26,65.2 v1(83.62,64.56) ; v1(188.63,31.67) 188.4,31.44 C113.2 ; C84.1 v1(79.3,86.28) ; J13.16 v1(185.86,39.93) ; C153.2 100.77,12.18 ; C153.2 101.83,11.43 ; C153.2 99.7,11.43 ; R111.2 v1(107.88,81.71) ; 17.6,69.77 C630.2 18.47,69.02 ; v1(135.57,130.6) 135.06,131.11 C33.2 ; C655.2 35.19,82.14 ; C655.2 35.19,80.01 ; C655.2 35.93,81.07 ; 88.04,96.35 C59.2 85.98,97.46 ; R147.1 v1(100.01,45.9) ; 51.36,83.92 C648.2 ; C648.2 51.36,87.37 ; C648.2 52.56,85.65 ; v1(175.82,141.91) 175.82,143.56 C13.2 176.71,143.43 v1(176.71,141.91) ; Y3.4 176.12,135.65 v1(176.08,135.68) ; R25.2 v1(192.72,140.26) ; v1(86.16,58.09) 85.91,57.83 C95.2 v1(87.31,55.8) ; C23.2 v1(137.09,135.68) ; Q19.3 v1(70.67,101.65) ; D11.C v1(76.88,92.11) ; C12.2 v1(194.24,143.56) ; P3.26 v1(46.16,135.18) ; R435.2 v1(16.82,90.73) ; C88.2 v1(84,68.76) ; C634.2 11.31,69.26 ; C634.2 9.58,68.07 ; C634.2 7.85,69.26 ; C7.1 v1(214.18,148.77) ; v1(108.51,40.94) 108.51,40.43 109.02,39.93 R151.2 ; P3.4 v1(46.03,123.18) ; R132.2 v1(214.31,59.74) ; C386.1 v1(75.11,62.15) ; C63.2 v1(142.93,112.57) ; v1(105.21,27.73) 106.86,27.73 107.28,28.15 C118.2 107.28,30.35 106.77,30.85 v1(105.21,30.85) ; R358.2 v1(60.64,91.36) ; v1(199.32,139.88) 200.21,139.88 200.72,140.38 C14.2 200.72,141.15 200.21,141.65 v1(199.19,141.65) ; P3.34 v1(46.06,138.38) ; v1(103.18,65.83) 102.77,66.25 C90.2 ; v1(176.97,140.13) 176.84,140 C17.2 175.32,140.64 175.57,140.89 v1(176.84,140.89) ; P2.15 v1(42.75,62.28) ; R449.1 67.11,87.81 v1(66.73,87.42) ; U27.3 v1(194.37,52.94) ; U14.10 v1(192.59,96.31) ; C127.2 v1(98.23,24.56) ; C93.2 v1(108.51,59.48) ; C638.2 v1(17.58,77.26) ; C637.1 v1(14.03,90.6) ; v1(192.97,134.03) 192.84,134.16 R38.2 ; P2.18 v1(38.35,54.09) ; C91.2 v1(84.51,60.37) ; C76.2 v1(149.95,104.66) ; C76.2 151.44,105.33 151.06,105.71 v1(149.92,105.71) ; C76.2 151.44,104.06 151.06,103.68 v1(150.04,103.68) ; v1(107.63,130.1) C42.2 ; 68.13,99.74 v1(68.13,101.65) ; v1(67.11,89.46) 67.49,89.08 R448.1 ; v1(181.79,146.23) 183.06,146.23 183.44,145.84 183.44,145.08 183.06,144.7 v1(181.92,144.7) ; 9.02,85.44 C636.2 ; C636.2 10.09,84.69 ; C636.2 11.16,85.44 ; C623.2 v1(20.5,66.98) ; R94.1 v1(103.18,104.32) ; C58.2 v1(147.88,112.57) ; C90.2 v1(101.66,68.88) ; v1(159.31,110.79) 160.33,110.79 160.71,110.41 C65.2 160.71,109.52 160.33,109.14 v1(159.31,109.14) ; C126.2 v1(94.8,27.48) ; C103.2 v1(108.13,48.69) ; C656.1 v1(30.03,85.01) ; R109.2 v1(107.88,83.61) ; C89.2 95.81,64.56 v1(96.2,64.18) ; C129.2 v1(96.7,26.87) ; v1(116.77,135.43) 116.34,135.43 Y2.2 ; R439.2 v1(32.31,66.34) ; C52.2 v1(209.48,122.22) ; R115.2 v1(89.34,77.9) ; v1(168.18,112.19) 168.18,113.1 167.82,113.46 C64.2 167.32,113.46 166.93,113.08 v1(166.93,112.06) ; C158.2 85.45,9.88 ; C158.2 85.45,7.74 ; C158.2 84.7,8.81 ; C119.2 v1(170.24,30.27) ; R128.2 v1(92.64,68.76) ; Y2.4 113.17,132.43 v1(112.83,132.76) C36.2 ; P2.26 v1(35.15,54.02) ; C62.2 v1(136.33,112.57) ; C134.2 v1(174.68,22.27) ; C11.2 v1(196.14,143.69) ; v1(141.15,119.94) 141.15,118.03 141.53,117.65 C54.2 141.79,117.65 142.15,118.01 v1(142.15,119.96) ; C100.1 v1(99.5,50.59) ; C116.2 86.04,15.03 v1(86.42,15.42) ; R28.1 v1(131.12,138.73) ; C161.2 v1(169.73,7.03) ; R441.2 v1(33.58,66.34) ; C24.2 v1(92.89,134.92) ; C164.2 85.45,7.59 ; C164.2 84.7,6.53 ; C164.2 85.45,5.46 ; C166.2 v1(99.12,1.7) ; C150.2 v1(174.55,12.62) ; 108.83,19.3 C136.2 108.83,21.44 ; C105.2 v1(100.51,43.74) ; R248.1 v1(78.92,54.66) ; C6.2 v1(205.67,151.18) ; C147.2 v1(101.15,14.78) ; R68.1 v1(122.48,124.64) ; R334.2 v1(60.25,71.55) ; R249.2 v1(74.22,44.63) ; P2.34 v1(31.95,54.02) ; 4.68,78.92 C639.2 6.41,80.11 ; C67.2 201.99,109.9 v1(201.61,109.52) ; C25.2 132.01,134.29 132.39,134.67 v1(132.39,134.97) Y1.4 ; R98.2 v1(178.87,96.82) ; C647.2 v1(157.54,105.97) ; C51.1 v1(110.04,122.35) ; v1(166.58,104.55) 166.58,105.35 166.93,105.71 C78.2 167.95,105.71 168.46,105.2 v1(168.46,104.57) ; P3.29 v1(54.35,136.38) ; R450.1 v1(63.68,64.44) ; v1(20.81,69.14) C622.2 v1(19.87,70.41) ; R475.2 v1(31.3,93.39) ; R126.2 v1(89.46,72.82) ; C97.2 v1(100.39,51.99) ; C107.2 82.61,40.69 82.97,41.05 v1(84.28,41.05) ; C107.2 82.61,39.04 83.11,38.53 v1(84.13,38.53) ; C107.2 v1(84.23,39.77) ; Q20.2 v1(72.57,106.86) ; R130.1 v1(214.18,62.41) ; R89.1 v1(212.4,112.57) ; C131.2 v1(174.68,23.8) ; R230.2 v1(71.94,93.9) ; R148.2 v1(90.35,42.59) ; C41.2 v1(191.7,130.35) ; v1(90.7,80.27) Y5.2 ; v1(90.7,80.27) 91.24,80.82 C85.2 ; 132.39,122.98 v1(133.66,122.98) ; C16.2 v1(166.55,140.13) ; J13.12 v1(192.59,36.88) ; C60.2 v1(119.18,103.05) ; R44.1 197.29,134.54 v1(197.67,134.92) ; v1(181.92,141.15) 183.06,141.15 183.44,141.53 183.44,142.42 182.94,142.92 v1(181.92,142.92) ; 211.38,119.94 v1(212.27,119.94) ; C29.2 v1(183.83,133.35) ; P3.18 v1(46.18,131.98) ; P3.40 v1(46.05,140.78) ; C144.2 v1(174.63,17.27) ; R20.1 v1(159.44,142.92) ; C43.1 v1(198.43,129.46) ; P3.27 v1(54.44,135.58) ; C137.2 v1(174.6,19.05) ; v1(101.59,123.25) 101.28,123.57 C45.2 ; R7.2 v1(170.11,153.08) ; R107.2 v1(107.88,85.77) ; P3.15 v1(54.56,127.58) ; R335.2 v1(70.03,78.53) ; P2.50 v1(25.55,53.99) ; R30.1 v1(110.55,138.48) ; R474.2 v1(31.3,92.12) ; C160.2 v1(167.7,7.16) ; R95.2 v1(133.79,102.16) ; C71.2 v1(207.32,107.62) ; R472.1 v1(29.9,86.41) ; R87.2 v1(133.66,112.06) ; C46.2 v1(133.91,124.38) ; C469.2 v1(57.08,78.92) ; C26.2 v1(112.83,134.16) ; C48.2 v1(110.55,123.75) ; 102.62,11.43 C154.2 ; C154.2 104.76,11.43 ; C154.2 103.69,12.18 ; 84.7,4.37 85.45,4.37 ; 85.45,4.37 85.45,5.43 ; 85.45,4.37 85.45,3.3 ; Y3.2 v1(173.24,132.21) 172.56,132.89 C31.2 ; SW3.9 v1(208.23,53.16) ; C650.2 v1(29.65,89.33) ; C643.2 16.39,69.26 ; C643.2 12.93,69.26 ; C643.2 14.66,68.07 ; 109.78,57.96 v1(110.67,57.96) ; R10.2 v1(198.05,148.26) ; R101.2 v1(180.27,96.82) ; U24.3 v1(194.37,56.88) ; v1(92,55.42) C94.2 v1(89.46,53.77) ; C141.2 v1(191.45,20.24) ; R470.2 v1(29.9,87.93) ; v1(140.88,121.82) 140.88,122.88 140.52,123.24 C49.2 139.25,123.24 138.99,122.98 v1(138.99,121.71) ; R352.2 v1(62.67,91.36) ; C654.2 v1(29.39,83.49) ; 84.72,23.72 C132.2 85.46,22.65 ; C125.2 v1(93.66,27.48) ; v1(214.31,58.09) R133.2 ; C159.2 v1(164.39,7.03) ; C20.2 v1(116.64,137.72) ; C22.2 115.37,136.57 v1(114.74,135.94) ; R6.2 v1(170.11,154.23) ; P3.9 v1(54.58,125.18) ; C120.2 v1(171.51,30.27) ; C142.1 v1(194.11,20.24) ; v1(94.04,83.11) 93.27,83.87 R104.1 ; R350.2 v1(64.06,74.47) ; R139.2 v1(214.31,54.79) ; C96.2 v1(93.66,54.66) ; R117.2 v1(107.77,77.77) ; C3.2 v1(185.73,152.19) ; v1(204.86,145.64) U3.1 ; R348.2 v1(62.29,71.55) ; R81.2 v1(212.78,117.14) ; R440.2 v1(34.85,66.34) ; C140.2 v1(190.18,20.24) ; R19.2 v1(192.72,141.91) ; C631.2 v1(18.34,90.98) ; U30.9 v1(180.65,28.5) ; C121.2 v1(172.65,30.27) ; P3.21 v1(54.45,133.18) ; R78.2 v1(205.54,121.59) ; U23.3 v1(196.27,60.82) ; P3.50 v1(46.24,144.78) ; C626.2 v1(59.16,140.51) ; R473.2 v1(31.3,95.93) ; Y1.2 v1(135.1,138.52) ; C39.2 v1(183.95,131.24) ; C5.2 v1(185.73,149.78) ; P2.21 v1(37.15,62.28) ; P2.4 v1(47.15,54.02) ; C151.2 v1(174.55,11.1) ; C32.1 v1(199.83,132.26) ; P2.29 v1(33.95,62.28) ; R88.2 v1(140.39,112.06) ; R437.1 v1(15.68,90.73) ; P2.27 v1(34.75,62.3) ; C635.2 v1(12.5,90.98) ; v1(83.83,59.92) C92.2 ; R21.2 v1(161.22,142.92) ; R433.2 v1(31.04,66.34) ; C146.2 v1(174.63,15.49) ; R345.2 v1(66.22,74.47) ; R234.2 v1(69.4,93.9) ; C98.2 v1(110.29,53.01) ; C148.2 v1(174.63,14.1)
  TOP w0.533: D6.A 67.42,141.4 ; D6.A 66.6,142.34 ; D6.A 66.6,140.46 ; D6.A 65.79,141.4 ; R5.2 69.14,156.63 ; R5.2 69.89,155.75 ; R5.2 69.14,154.87 ; J1.2 68.17,165.65 ; J1.2 65.99,166.73 ; J1.2 63.81,165.65 ; J1.2 65.99,164.57 ; C9.2 66.59,138.73 ; C9.2 65.84,139.61 ; C9.2 65.84,137.86
  L2_GND w0.762: J12.2 84,77.19 ; J12.2 82.93,76.12 ; J12.2 85.07,76.12 ; J12.2 84,75.05 ; SW4.2 208.23,159.74 ; SW4.2 209.37,158.61 ; SW4.2 208.23,157.47 ; SW4.2 207.1,158.61 ; J14.2 92.39,32.87 ; J14.2 93.46,31.8 ; J14.2 92.39,30.73 ; J14.2 91.32,31.8 ; 63.8,165.65 J1.2 ; J1.2 68.18,165.65 ; J1.2 65.99,164.57 ; J1.2 65.99,166.73 ; BT1.3 129.12,110.11 ; BT1.3 127.99,111.24 ; BT1.3 126.85,110.11 ; BT1.3 127.99,108.98 ; 179.76,129.15 J7.7 ; J7.7 180.83,130.22 ; J7.7 178.69,130.22 ; J7.7 179.76,131.29 ; 212.91,151.25 J6.2 ; J6.2 213.98,152.32 ; J6.2 212.91,153.39 ; J6.2 211.84,152.32 ; J8.2 178.29,123.37 ; J8.2 177.22,122.3 ; J8.2 177.22,124.43 ; J8.2 176.15,123.37 ; 205.6,156.11 SW4.4 ; SW4.4 208.37,156.11 ; SW4.4 206.98,154.72 ; SW4.4 206.98,157.49 ; 52,2.47 BH3.1 ; BH3.1 49.47,5 ; BH3.1 52,7.53 ; BH3.1 54.53,5 ; 176.49,162.1 P1.4 ; BH4.1 209.5,7.53 ; BH4.1 212.03,5 ; BH4.1 206.97,5 ; BH4.1 209.5,2.47 ; J5.19 130.56,142.95 ; J5.19 130.56,140.69 ; J5.19 129.42,141.82 ; J5.19 131.69,141.82 ; 209.5,134.47 BH2.1 ; BH2.1 206.97,137 ; BH2.1 209.5,139.53 ; BH2.1 212.03,137 ; 213.98,154.72 SW4.3 ; SW4.3 213.98,157.49 ; SW4.3 212.6,156.11 ; 145.73,101.59 J9.3 ; J9.3 145.73,103.73 ; J9.3 146.8,102.66 ; J9.3 144.66,102.66 ; 119.71,7 D12.3 118.54,8.17 ; J9.1 140.65,103.73 ; J9.1 139.58,102.66 ; J9.1 140.65,101.59 ; J9.1 141.72,102.66 ; J4.19 105.56,142.95 ; J4.19 106.69,141.82 ; J4.19 104.42,141.82 ; J4.19 105.56,140.69 ; D13.3 126.54,8.17 ; P1.5 177.51,165.99 ; BH1.1 54.53,160 ; BH1.1 49.47,160 ; BH1.1 52,157.47 ; BH1.1 52,162.53
  L5_PWR w0.127: SW4.2 208.23,159.74 ; SW4.2 208.23,157.47 ; SW4.2 209.36,158.61 ; SW4.2 207.1,158.61 ; J1.2 68.17,165.65 ; J1.2 65.99,166.73 ; J1.2 63.81,165.65 ; J1.2 65.99,164.57 ; 206.98,154.72 SW4.4 ; SW4.4 206.98,157.49 ; SW4.4 205.6,156.11 ; SW4.4 208.37,156.11 ; 52,157.47 BH1.1 ; BH1.1 52,162.53 ; BH1.1 49.47,160 ; BH1.1 54.53,160 ; 130.56,140.69 J5.19 ; J5.19 131.69,141.82 ; J5.19 129.43,141.82 ; J5.19 130.56,142.95 ; J4.19 105.56,142.95 ; J4.19 105.56,140.69 ; J4.19 104.43,141.82 ; J4.19 106.69,141.82 ; 212.6,156.11 SW4.3 ; SW4.3 213.98,154.72 ; SW4.3 213.98,157.49 ; J6.2 213.98,152.32 ; J6.2 211.84,152.32 ; J6.2 212.91,153.39 ; 49.47,5 BH3.1 ; BH3.1 54.53,5 ; BH3.1 52,7.53
  BOTTOM w0.203: U44.6 192.66,44.81 v1(193.73,43.74) ; U44.7 192.26,44.17 191.83,43.74 v1(191.32,43.74) 191.32,44.46 191.86,45.01 U44.8
  BOTTOM w0.254: C461.2 176.59,56.06 v1(176.84,56.31) ; v2(142.2,70.01) 142.2,69.54 142.53,69.21 C342.2 ; v2(145.4,62.81) 145.4,63.24 145.04,63.6 C398.2 ; C561.2 136.62,19.2 v2(136.72,19.3) ; v2(142.2,62.81) 142.3,62.91 C399.2 ; v1(184.33,53.39) 184.59,53.64 C466.2 ; v2(138.31,16.86) 138.28,16.89 C573.2 ; C385.2 145.33,64.47 v2(145.4,64.41) ; C542.2 137.41,21.45 137.16,21.7 v2(136.72,21.7) ; C331.2 139.7,72.31 v2(139.8,72.41)
  BOTTOM w0.305: v2(115.55,24.9) 115.06,24.9 114.9,25.05 C500.2 C488.2 ; C501.2 v2(156.14,26.49) ; v2(143.49,19.3) 143.49,19.39 C547.2 ; v2(164.66,21.7) 164.67,21.69 165.11,21.69 165.32,21.91 C530.2 ; C489.2 156.24,27.3 v2(156.09,27.15) ; v2(143,68.41) 143.07,68.34 C348.2 ; C504.2 161.61,26.07 v2(161.32,26.36) ; C560.2 150.59,19.2 v2(150.69,19.3) ; v1(126.68,47.93) 126.71,47.97 C475.2 ; C574.2 v2(124.44,16.89) ; v2(149.89,25.7) 149.89,25.7 C505.2 ; U15.15 v1(180.55,86.64) ; v1(206.56,113.59) 206.43,113.46 R233.1 ; C502.2 v2(142.27,26.49) ; C482.2 v1(142.04,31.8) ; C345.2 140.02,68.63 v2(139.8,68.41) ; C580.2 96.2,16.56 95.94,16.81 v1(95.94,17.32) ; v1(123.25,60.25) 123.88,60.25 124.01,60.37 C441.2 ; 207.07,116.13 206.81,116.13 206.56,115.87 v1(206.56,115.36) ; v2(122.75,21.7) 123.21,21.7 123.44,21.47 C543.2 ; C548.2 129.84,20.18 129.52,19.86 129.52,19.3 v2(129.52,19.3) ; v1(120.96,69.01) 121.47,69.01 121.63,69.17 C341.2 ; C454.2 129.47,57.45 129.22,57.2 129.22,56.94 v1(129.09,56.82) ; U15.8 v1(184.45,89.59) ; v2(135.92,25.7) 135.9,25.68 C506.2 ; C363.2 139.81,66.8 v2(139.8,66.81) ; C562.2 122.65,19.2 v2(122.75,19.3) ; v2(115.55,19.3) 115.55,19.39 C546.2 ; C483.2 v1(140.14,31.16) ; C491.2 C503.2 v2(128.1,26.49) ; C470.2 v1(153.6,50.09) ; C400.2 139.88,62.9 v2(139.8,62.81) ; C572.2 152.2,16.91 v1(152.25,16.86) ; v2(121.95,25.7) 121.93,25.68 C507.2 ; C569.2 115.51,16.94 v2(115.55,16.9) ; C526.2 v2(156.06,23.29) ; v1(93.4,46.15) 93.15,46.4 C478.2 ; v2(157.46,19.3) 157.46,19.53 158.08,20.15 C549.2 ; C380.2 140.06,64.95 v2(139.8,65.21) ; C571.2 164.67,17.93 164.51,18.1 C559.2 164.51,19.15 v2(164.66,19.3) ; v2(138.19,62.81) 138.06,62.95 C396.2 ; v2(143.49,24.1) 143.11,24.1 142.84,23.84 C527.2 ; v1(138.99,31.04) 138.49,30.53 C484.2 ; C531.2 151.38,21.93 151.14,21.69 150.7,21.69 v2(150.69,21.7) ; C266.1 156.9,124.98 156.87,125.02 ; C311.2 v1(156.52,81.33) ; v2(136.6,64.41) 136.2,64.02 136.2,63.64 ; C490.2 v2(141.99,27.3) ; C359.2 v2(145.4,66.01) ; C528.2 128.85,23.81 129.14,24.1 129.52,24.1 v2(129.52,24.1) ; C297.2 v1(144.46,86.28) ; C529.2 114.9,23.81 115.19,24.1 v2(115.55,24.1) ; C337.2 151.97,70.9 152.22,71.14 C336.1 ; C476.2 v1(155.25,45.13) 155.21,45.17 C479.2
  BOTTOM w0.381: v1(168.08,126.16) 167.82,126.41 C246.1 ; C270.1 163.76,122.91 v1(163.94,123.08) ; v1(152.9,123.05) 153.09,123.24 C265.1 ; v1(153.94,134.09) 153.94,134.09 153.12,133.27 C223.1 ; v1(156.93,129.08) C244.1 ; 189.29,88.31 189.29,88.92 v2(189.43,89.06) ; 155.76,131.11 154.97,131.11 v1(154.93,131.08) ; v1(25.55,53.99) 25.46,54.08 C324.2 ; C271.1 150.93,123.08 v1(150.95,123.1) ; v2(136.72,27.3) 137.03,27.61 R374.1 ; C243.1 v1(158.93,129.08) ; v1(169.6,129.59) 169.22,129.21 C240.1 ; C275.2 C280.1 154.95,120.06 v1(154.93,120.08) ; 177.35,70.15 177.35,67.69 v1(177.09,67.43) ; C267.1 160.65,123.37 v1(160.93,123.08) ; v1(157.99,121.14) 158.19,121.33 C272.1 ; v1(161.94,127.09) 161.98,127.05 C248.1 163.25,127.05 163.38,127.18 C253.1 ; C218.1 149.89,133.3 v1(149.89,134.13) 149.92,134.16 C216.1 ; v1(134.42,15.03) 134.17,15.29 134.17,17.7 ; C224.1 155,132.13 v1(154.99,132.14) ; v2(122.75,27.3) 123.19,27.73 R373.1 ; v1(152.96,128.06) 152.84,127.94 C249.1 ; C219.1 159.82,132.19 v1(159.93,132.08) ; C274.2 151.06,121.21 v1(150.93,121.08) 150.92,121.06 150.92,120.46 151.19,120.19 C279.1 ; v1(133.28,80.44) 133.28,80.82 133.66,81.2 R404.2 ; v1(37.39,57.45) 37.01,57.07 C306.2 ; v1(157.9,132.11) 158.14,131.87 C227.1 ; C239.1 161.95,130.1 v1(161.93,130.08) ; v1(148.27,15.03) 148.01,15.29 C575.2 C566.2 ; C565.2 C578.2 v1(161.98,15.16) ; v1(158.93,127.08) C254.1 ; 153.73,130.1 153.73,130.86 153.95,131.08 v1(153.95,131.08) ; v2(148.6,62.81) 148.8,63.01 C402.1 ; C220.1 155.89,134.03 v1(155.95,134.1) ; 100.64,133.02 v1(101.66,133.02) ; 157.79,131.11 v1(156.9,131.11) ; C256.1 152.84,125.98 v1(151.93,125.08) ; v1(152.84,14.02) 152.08,13.26 C593.2 ; C322.2 35.24,54.11 v1(35.15,54.02) ; R372.1 151.13,27.73 v2(150.69,27.3) ; C229.2 100.39,132 v1(101.66,132) ; C568.2 C577.2 v1(120.2,15.02) ; C252.1 156.9,127.05 v1(156.93,127.08) ; C278.2 160.06,120.08 v1(160.93,120.08) 161.04,120.19 C277.2 C276.1 ; C471.2 v1(149.79,49.07) ; v1(47.15,54.02) 47.3,54.17 C321.2 ; C182.1 v1(175.82,150.16) ; C307.2 v1(25.84,57.33) ; R315.1 197.41,70.03 198.18,69.26 v1(199.7,69.26) ; C242.1 v1(160.93,129.08) ; C273.2 v1(154.93,121.08) ; R402.2 v1(193.73,68.37) ; C269.2 155.95,122.1 v1(156.93,123.08) ; R371.1 165.22,27.86 v2(164.66,27.3) ; C245.1 151.06,128.95 v1(150.93,129.08) ; C263.1 v1(150.93,125.08) ; C259.1 156.87,125.02 v1(156.93,125.08) ; C308.2 v1(47.05,57.45)
  BOTTOM w0.508: 83.62,118.16 83.62,117.4 83.37,117.14 C40.2 ; v1(102.93,132) 102.8,131.87 C236.1 ; C167.1 104.01,160.68 ; C167.1 101.09,160.68 ; C167.1 102.55,161.81 ; 92.64,11.36 C592.2 93.52,12.11 ; v1(54.33,138.78) 53.82,139.29 C443.2 ; C234.1 126.04,131.62 v1(126.42,132) ; R336.2 v1(116.01,51.99) ; 98.48,10.98 C596.2 97.61,11.73 ; Q3.3 85.32,121.59 ; Q3.3 82.68,121.59 ; Q3.3 84,120.96 ; v1(101.66,135.05) 101.28,135.43 C206.1 ; v1(166.93,124.08) C257.1 C258.1 ; v1(168.84,7.8) 168.84,8.3 C606.2 ; C194.1 v1(158.04,139.88) ; C192.1 v1(147.25,142.03) ; v1(46.18,131.98) 46.54,131.62 C463.2 ; R353.1 v1(160.46,49.07) ; v1(165.94,134.07) 165.92,134.05 R206.2 ; 164.7,155.5 C172.1 ; C172.1 166.43,154.3 ; C172.1 168.15,155.5 ; 114.48,155.6 C169.1 ; C169.1 112.58,156.79 ; C169.1 116.39,156.79 ; C410.2 v1(123.25,60.25) ; C21.2 85.15,126.31 ; C21.2 83.24,127.51 ; C21.2 81.34,126.31 ; C21.2 83.24,125.12 ; 93.92,11.73 C598.2 ; C598.2 94.8,10.98 ; C598.2 95.68,11.73 ; R340.1 139.25,50.47 139.76,49.96 v1(140.14,49.96) ; C179.1 v1(163.76,150.42) ; 101.78,17.97 C556.2 ; C556.2 102.53,18.84 ; C556.2 101.78,19.72 ; v1(46.03,123.18) 46.23,122.98 C456.2 ; R211.2 R215.2 R219.2 175.95,127.3 v1(176.84,128.19) ; C215.1 105.85,134.03 v1(105.21,134.03) ; 126.8,157.01 C168.1 ; C168.1 128.26,158.14 ; C168.1 125.34,158.14 ; v1(154.23,72.82) 154.97,72.08 C334.2 153.98,71.57 C335.1 152.58,71.17 C336.1 ; C600.2 C605.2 168.59,10.08 168.08,10.59 168.08,11.48 v1(167.82,11.73) ; C81.2 v1(170.87,96.19) ; C191.1 144.71,143.3 v1(144.33,142.92) ; 84,118.42 Q3.1 ; Q3.1 85.32,119.05 ; Q3.1 82.68,119.05 ; Q3.1 84,119.67 ; v1(186.24,153.72) 186.24,155.12 186.62,155.5 C171.1 ; v1(98.35,80.19) 98.61,80.19 C309.2 ; C458.2 46.41,144.96 v1(46.24,144.78) ; C404.2 154.74,62.61 154.34,63.01 C401.1 C402.1 ; 161.85,153.72 v1(162.62,153.72) ; C315.2 v1(145.85,80.57) ; C595.2 v1(138.99,14.02) ; 87.37,126.16 C27.2 ; C27.2 88.12,125.09 ; C27.2 88.12,127.23 ; FL2.2 v1(116.39,59.61) ; v1(165.93,136.08) 166.2,135.81 C213.1 ; J16.11 v1(200.2,8.8) ; C468.2 127.31,53.13 v1(126.42,54.02) ; R203.2 169.83,135.07 v1(167.93,135.07) ; C425.2 118.29,61.01 117.91,60.63 v1(117.91,59.74) C450.2 ; v1(132.52,131.49) 132.9,131.11 R213.1 ; v1(86.16,22.78) 85.78,22.4 C551.2 C563.2 C579.2 85.78,16.05 v1(86.42,15.42) ; R305.2 v1(113.98,72.95) ; v1(184.33,58.85) 184.59,59.1 C444.2 ; C320.2 151.31,76.12 v1(152.08,76.88) ; C241.2 v1(120.2,128.83) 120.2,129.46 120.58,129.84 C233.2 ; v1(145.34,107.74) 145.47,107.62 C284.2 ; C594.2 v1(143.57,14.02) ; v1(164.9,123.05) 164.9,124.76 164.52,125.14 C260.1 ; R284.2 144.71,75.36 R298.1 144.6,74.1 v2(144.6,72.41) ; R349.2 v1(160.33,50.21) ; v1(95.94,22.4) 96.45,21.89 C534.2 ; 211.38,84.88 v1(212.27,84.88) ; v1(94.42,46.15) 94.93,45.64 R359.2 ; C211.1 154.82,136.19 v1(154.93,136.08) ; v1(120.96,69.01) 120.96,68.5 121.85,67.61 C367.2 ; v1(105.21,135.05) 105.34,135.18 C203.1 ; C205.1 102.42,135.56 v1(102.93,135.05) ; T1.4 79.05,126.34 ; T1.4 80.37,125.46 ; T1.4 79.05,124.58 ; C190.2 v1(139.5,144.32) ; v1(125.28,135.05) 125.53,135.3 125.53,135.94 ; v2(188.63,84.26) 188.63,83.64 C301.2 ; v1(122.87,135.05) 122.48,135.43 122.48,135.94 ; C524.2 92.89,22.53 v1(93.02,22.4) ; v1(126.68,47.93) 125.91,48.69 C473.2 ; 211.38,71.04 v1(212.27,71.04) ; C196.1 v1(153.98,139.88) ; v2(149.4,68.41) 151.28,68.41 C357.1 C356.1 153.8,68.17 C358.2 ; v1(126.42,135.05) 126.68,135.3 126.68,135.94 ; R207.1 v1(93.53,132.51) ; C314.2 98.35,79.17 v1(98.23,79.3) ; R346.2 v1(160.33,51.36) ; v1(174.43,83.23) 174.94,83.74 Q22.3 ; v1(94.54,17.32) 94.16,16.94 C581.2 ; 211.38,74.85 v1(212.27,74.85) ; 211.38,81.07 v1(212.27,81.07) ; v1(127.82,14.02) C603.2 C604.2 ; v1(88.58,63.17) 88.19,62.79 C408.1 ; 211.38,83.61 v1(212.27,83.61) ; v1(76.51,118.92) 76.49,118.94 76.49,119.17 Q17.3 ; v1(129.09,56.82) 128.58,56.31 C460.2 ; C422.1 121.98,60.25 v1(122.1,60.12) C451.1 ; C221.1 v1(122.87,133.02) ; 113.85,144.45 v1(114.61,144.45) ; 211.38,82.34 v1(212.27,82.34) ; C298.2 C299.2 v1(141.41,86.28) ; C296.2 192.17,85.52 v2(192.63,85.06) ; C195.1 v1(156.01,139.88) ; C225.1 C226.1 160.97,133.05 v1(160.94,133.07) ; R339.1 140.26,50.72 140.14,50.59 v1(140.14,49.96) ; v1(172.65,30.27) 172.17,29.79 C485.2 ; C597.2 97.58,11.73 ; C597.2 96.7,10.98 ; C597.2 95.83,11.73 ; C310.2 C312.2 v1(152.96,81.84) ; v1(187.13,153.72) C171.1 ; C171.1 187.76,155.5 188.12,155.14 v1(188.12,153.82) ; v1(192.72,140.26) 192.92,140.05 Q16.2 ; v1(142.17,130.48) 142.2,130.44 U41.4 ; R269.1 v1(165.41,79.8) ; C545.2 96.07,20.62 v1(95.94,20.5) ; v1(93.02,17.32) 92.64,16.94 C582.2 ; R210.1 v1(93.53,130.99) ; v1(107.24,43.1) 107.75,43.61 R361.2 ; v1(96.07,75.23) 96.32,75.49 C325.2 ; v1(156.93,136.08) 156.82,136.19 C210.1 ; C370.2 90.35,66.47 v1(89.59,65.71) ; C564.2 96.45,17.83 v1(95.94,17.32) ; C428.2 v1(49.71,144.57) ; C287.2 v1(196.65,96.57) ; v1(115.37,61.77) FL1.2 ; C368.2 v1(119.82,69.01) ; v1(98.35,81.07) 98.74,81.46 C302.2 ; v1(38.35,54.09) 38.66,54.4 C326.2 ; C214.1 127.69,134.54 127.18,134.03 v1(126.42,134.03) ; C608.2 v1(110.29,3.35) ; R399.2 v1(172.01,2.97) ; C423.1 120.45,60.5 v1(120.83,60.12) C452.1 ; C440.2 49.33,133.4 v1(49.71,133.02) ; R338.1 141.28,50.47 140.77,49.96 v1(140.14,49.96) ; v1(104.07,132) 103.94,131.87 C235.1 ; v1(179.76,77.14) 179.25,77.65 C317.2 ; Q3.2 85.32,120.32 ; Q3.2 84,119.69 ; Q3.2 84,120.94 ; Q3.2 82.68,120.32 ; R341.1 138.11,50.34 v1(137.85,50.09) 137.34,50.09 137.09,50.34 R342.1 ; R320.2 v1(88.58,65.71) ; 109.02,64.31 v1(108.01,64.31) ; J16.3 v1(188.63,31.67) ; C209.1 158.82,136.19 v1(158.93,136.08) 159.08,135.94 C212.1 ; 102.53,20.62 C544.2 101.78,19.75 ; U40.2 197.03,154.35 197.54,153.85 v1(198.56,153.85) ; R204.1 v1(71.05,114.73) ; v1(105.59,128.45) 105.34,128.19 C251.2 ; v1(107.24,42.09) 106.99,41.83 C480.2 ; C228.1 123.37,131.49 v1(122.87,132) ; 123.63,135.94 123.63,135.56 v1(124.14,135.05) ; v1(100.39,128.7) 100.13,128.45 C247.2 ; C590.2 v1(89.34,14.27) ; 211.38,68.5 v1(212.27,68.5) ; v1(182.3,28.24) 181.93,28.62 J16.6 ; C193.1 v1(197.54,140.64) ; 211.38,87.42 v1(212.4,87.42) ; v1(96.58,81.07) 96.2,81.46 C305.2 ; C316.2 v1(144.2,80.57) ; v1(168.56,149.55) 168.56,147.85 168.2,147.5 C185.2 167.82,147.5 167.44,147.88 v1(167.44,149.53) ; R270.1 v1(165.41,78.79) ; 211.38,78.53 v1(212.27,78.53) ; v1(95.81,18.97) 95.94,18.84 C557.2 ; v1(91.24,18.97) 90.99,18.72 C558.2 ; 211.38,86.15 v1(212.27,86.15) ; v1(128.96,128.57) 127.69,127.3 C250.2 ; C486.2 171.02,29.79 v1(171.51,30.27) ; R258.1 v1(172.27,82.73) ; 126.8,86.92 125.28,86.92 v1(125.28,87.81) ; 128.33,86.92 v1(128.33,87.81) ; C304.2 92.51,81.46 v1(92.89,81.84) ; C204.1 103.94,135.18 v1(104.07,135.05) ; C283.2 v1(138.74,107.74) ; v1(151.93,135.08) 151.41,135.08 151.06,135.43 C207.1 ; C327.2 v1(95.56,73.96) ; R202.2 176.33,139.62 176.84,140.13 v1(176.97,140.13) ; C462.2 v1(160.97,55.04) ; C198.2 v1(146.23,138.73) ; C187.1 v1(143.19,144.96) ; C237.1 v1(101.66,132) ; C285.2 v1(197.92,105.71) ; D25.1 v1(70.47,117.09) ; C646.2 v1(156.77,92.76) ; 211.38,79.8 v1(212.27,79.8) ; R278.1 133.41,80.31 v1(133.28,80.44) ; R271.2 150.17,79.17 v1(150.81,79.8) ; C611.2 103.05,53.39 v1(103.43,53.77) ; R425.2 124.77,72.18 v1(125.15,71.8) 126.29,71.8 126.68,72.18 R426.2 ; C230.1 124.77,131.49 v1(125.28,132) ; v1(103.43,56.94) 102.93,57.45 R327.2 ; C525.2 90.73,22.91 v1(91.24,22.4) ; v1(149.79,49.07) 147.5,49.07 146.74,49.83 C472.2 ; Q22.1 v1(177.48,83.49) ; C439.2 v1(49.71,123.49) ; v1(170.24,30.27) 169.75,29.79 C487.2 ; 109.02,65.96 v1(108.01,65.96) ; 211.38,73.58 v1(212.27,73.58) ; C197.1 v1(151.95,139.88) ; R354.1 v1(160.46,47.8) ; C602.2 C601.2 136.84,11.73 137.34,11.22 v1(137.34,8.94) ; 211.38,72.31 v1(212.4,72.31) ; C303.2 97.21,81.33 v1(97.47,81.07) ; v1(46.16,135.18) 46.29,135.05 C457.2 ; C369.2 117.91,68.76 v1(117.53,69.14) ; v1(176.01,7.6) J16.12 ; C180.2 v1(166.93,150.16) ; C570.2 91.12,17.45 v1(91.24,17.32) 91.24,17.19 C583.2 ; v1(93.4,76.63) 92.77,76.63 92.26,77.14 C319.2 92.26,78.79 92.77,79.3 ; C300.2 v1(30.99,62.02) ; C318.2 97.85,78.41 97.47,78.79 v1(97.47,79.3) ; v1(91.24,20.5) 90.99,20.24 C550.2 ; C289.1 v1(174.94,94.54) ; R214.1 v1(93.53,129.46) ; C292.2 v1(123.75,88.69) ; Q28.2 v1(159.77,6.27) ; C599.2 v1(156.9,14.02) ; 211.38,65.96 v1(212.15,65.96) ; 211.38,69.77 v1(212.27,69.77) ; C607.2 v1(110.04,7.29) ; C455.2 84.51,57.58 v1(85.15,58.21) ; C288.1 v1(176.21,94.54) ; 200.21,114.86 v1(200.21,115.75) ; R337.2 v1(160.33,52.5)
  vias: v1(3.23,81.71) v1(3.36,83.87) v1(4.25,80.69) v1(4.37,82.85) v1(5.26,81.71) v1(5.39,83.87) v1(6.28,80.82) v1(6.41,82.98) v1(7.3,65.96) v1(8.18,67.1) v1(9.33,66.09) v1(10.34,67.1) v1(11.36,66.09) v1(11.99,69.64) v1(12.38,68.5) v1(12.38,67.1) v1(13.39,66.22) v1(14.28,84) v1(14.79,67.1) v1(15.3,85.01) v1(15.3,84) v1(15.8,66.22) v1(16.31,85.01) v1(16.31,84) v1(16.69,67.1) v1(17.84,68.88) v1(17.84,67.61) v1(17.84,66.22) v1(35.62,87.3) v1(35.62,86.28) v1(36.63,87.3) v1(36.63,86.28) v1(36.63,85.27) v1(36.76,78.53) v1(37.78,77.52) v1(37.78,76.25) v1(38.79,78.53) v1(38.79,75.23) v1(39.81,77.65) v1(39.81,76.25) v1(40.82,75.36) v1(49.84,76.5) v1(50.86,75.49) v1(51.87,76.5) v1(52,83.49) v1(52,78.41) v1(52.89,75.61) v1(53.02,82.47) v1(53.02,77.39) v1(54.03,83.49) v1(54.03,78.41) v1(54.16,87.42) v1(54.16,85.39) v1(55.05,82.6) v1(55.05,77.52) v1(55.17,86.41) v1(55.17,84.5) v1(70.16,120.83) v1(70.29,119.56) v1(70.29,118.54) v1(81.08,9.95) v1(81.21,5.89) v1(81.46,7.67) v1(82.1,9.32) v1(82.1,6.65) v1(82.35,10.84) v1(83.11,6.78) v1(84.38,10.59) v1(84.38,8.81) v1(84.38,6.53) v1(85.78,125.02) v1(85.91,126.41) v1(85.91,95.17) v1(85.91,93.39) v1(86.16,28.24) v1(86.16,26.59) v1(86.16,25.19) v1(86.16,23.92) v1(86.29,11.35) v1(86.54,127.3) v1(86.54,124) v1(87.05,126.41) v1(87.05,125.14) v1(87.94,95.17) v1(88.07,93.39) v1(88.58,64.56) v1(89.59,64.56) v1(89.59,63.17) v1(93.02,20.5) v1(93.02,18.97) v1(93.4,48.82) v1(93.4,47.42) v1(94.42,47.42) v1(94.54,22.4) v1(94.54,20.5) v1(94.54,18.97) v1(96.58,80.19) v1(96.58,79.3) v1(97.47,80.19) v1(99.24,41.32) v1(100.01,153.97) v1(100.01,152.83) v1(100.51,12.62) v1(100.77,153.34) v1(101.02,47.67) v1(101.66,134.03) v1(101.66,45.9) v1(101.91,12.62) v1(102.04,15.8) v1(102.93,134.03) v1(102.93,133.02) v1(103.31,55.29) v1(103.43,43.1) v1(103.43,42.09) v1(103.56,15.67) v1(103.69,12.62) v1(103.94,14.91) v1(104.07,134.03) v1(104.07,133.02) v1(104.45,88.19) v1(104.45,15.67) v1(104.58,43.1) v1(104.58,42.09) v1(104.7,55.29) v1(104.7,53.77) v1(104.83,56.94) v1(105.09,14.91) v1(105.09,12.62) v1(105.21,133.02) v1(105.21,132) v1(105.21,26.46) v1(105.97,55.29) v1(105.97,53.77) v1(105.97,43.1) v1(105.97,42.09) v1(107.24,12.62) v1(107.5,11.73) v1(111.49,154.1) v1(112.25,155.12) v1(113.01,154.1) v1(114.66,154.1) v1(115.8,154.86) v1(116.57,154.1) v1(117.58,154.99) v1(118.22,153.97) v1(122.87,134.03) v1(124.14,134.03) v1(124.14,133.02) v1(124.14,132) v1(125.28,134.03) v1(125.28,133.02) v1(125.79,155.88) v1(126.42,133.02) v1(126.8,155.88) v1(127.9,155.96) v1(135.57,108.89) v1(137.09,110.16) v1(137.09,108.89) v1(137.09,107.74) v1(138.74,110.16) v1(138.74,108.89) v1(142.17,108.89) v1(143.69,110.16) v1(143.69,108.89) v1(143.69,107.74) v1(145.34,110.16) v1(145.34,108.89) v1(164.27,153.59) v1(164.78,152.96) v1(165.41,153.59) v1(166.05,152.96) v1(166.68,153.59) v1(167.95,153.59) v1(181.03,106.86) v1(182.53,106.96) v1(184.86,106.71) v1(185.73,78.15) v1(186.37,106.73) v1(187.51,78.15) v1(188.91,106.73) v1(190.43,145.84) v1(190.43,144.19) v1(190.56,106.73) v1(191.45,145.84) v1(191.45,144.19) v1(191.95,134.03) v1(191.95,132.38) v1(192.46,133.27) v1(192.97,132.38) v1(194.24,107.36) v1(196.53,107.36) v1(199.07,107.36) v1(204.78,115.36) v1(204.78,114.48) v1(204.78,113.59) v1(205.67,114.48) v1(206.56,114.48) v3(2.6,51.48) v3(2.6,48.94) v3(2.6,46.4) v3(2.6,41.32) v3(2.6,38.78) v3(2.6,36.24) v3(2.6,31.16) v3(2.6,28.62) v3(2.6,26.08) v3(2.6,21) v3(2.6,18.46) v3(2.6,13.38) v3(2.6,10.84) v3(3.87,166.29) v3(3.87,163.75) v3(3.87,161.21) v3(3.87,156.13) v3(3.87,153.59) v3(3.87,151.05) v3(3.87,140.89) v3(3.87,135.81) v3(3.87,133.27) v3(3.87,130.73) v3(3.87,125.65) v3(3.87,115.49) v3(3.87,112.95) v3(3.87,110.41) v3(3.87,105.33) v3(3.87,102.79) v3(3.87,100.25) v3(5.14,51.48) v3(5.14,48.94) v3(5.14,46.4) v3(5.14,41.32) v3(5.14,38.78) v3(5.14,36.24) v3(5.14,31.16) v3(5.14,28.62) v3(5.14,26.08) v3(5.14,21) v3(5.14,18.46) v3(5.14,13.38) v3(5.14,10.84) v3(6.41,166.29) v3(6.41,163.75) v3(6.41,161.21) v3(6.41,156.13) v3(6.41,153.59) v3(6.41,151.05) v3(6.41,140.89) v3(6.41,135.81) v3(6.41,133.27) v3(6.41,130.73) v3(6.41,125.65) v3(6.41,115.49) v3(6.41,112.95) v3(6.41,110.41) v3(6.41,105.33) v3(6.41,102.79) v3(6.41,100.25) v3(7.68,51.48) v3(7.68,48.94) v3(7.68,46.4) v3(7.68,41.32) v3(7.68,38.78) v3(7.68,36.24) v3(7.68,31.16) v3(7.68,28.62) v3(7.68,26.08) v3(7.68,21) v3(7.68,18.46) v3(7.68,13.38) v3(7.68,10.84) v3(8.95,166.29) v3(8.95,163.75) v3(8.95,161.21) v3(8.95,156.13) v3(8.95,153.59) v3(8.95,151.05) v3(8.95,145.97) v3(8.95,143.43) v3(8.95,140.89) v3(8.95,135.81) v3(8.95,133.27) v3(8.95,130.73) v3(8.95,125.65) v3(8.95,123.11) v3(8.95,120.57) v3(8.95,115.49) v3(8.95,112.95) v3(8.95,110.41) v3(8.95,105.33) v3(8.95,102.79) v3(8.95,100.25) v3(12.76,51.48) v3(12.76,48.94) v3(12.76,46.4) v3(12.76,41.32) v3(12.76,38.78) v3(12.76,36.24) v3(12.76,31.16) v3(12.76,28.62) v3(12.76,26.08) v3(12.76,21) v3(12.76,18.46) v3(12.76,13.38) v3(12.76,10.84) v3(14.03,166.29) v3(14.03,163.75) v3(14.03,161.21) v3(14.03,156.13) v3(14.03,153.59) v3(14.03,151.05) v3(14.03,145.97) v3(14.03,143.43) v3(14.03,140.89) v3(14.03,135.81) v3(14.03,133.27) v3(14.03,130.73) v3(14.03,125.65) v3(14.03,123.11) v3(14.03,120.57) v3(14.03,115.49) v3(14.03,112.95) v3(14.03,110.41) v3(14.03,105.33) v3(14.03,102.79) v3(14.03,100.25) v3(15.3,51.48) v3(15.3,48.94) v3(15.3,46.4) v3(15.3,41.32) v3(15.3,38.78) v3(15.3,36.24) v3(15.3,31.16) v3(15.3,28.62) v3(15.3,26.08) v3(15.3,21) v3(15.3,18.46) v3(15.3,13.38) v3(15.3,10.84) v3(16.57,166.29) v3(16.57,163.75) v3(16.57,161.21) v3(16.57,156.13) v3(16.57,153.59) v3(16.57,151.05) v3(16.57,145.97) v3(16.57,143.43) v3(16.57,140.89) v3(16.57,135.81) v3(16.57,133.27) v3(16.57,130.73) v3(16.57,125.65) v3(16.57,123.11) v3(16.57,120.57) v3(16.57,115.49) v3(16.57,112.95) v3(16.57,110.41) v3(16.57,105.33) v3(16.57,102.79) v3(16.57,100.25) v3(17.84,51.48) v3(17.84,48.94) v3(17.84,46.4) v3(17.84,41.32) v3(17.84,38.78) v3(17.84,36.24) v3(17.84,31.16) v3(17.84,28.62) v3(17.84,26.08) v3(17.84,21) v3(17.84,18.46) v3(17.84,13.38) v3(17.84,10.84) v3(19.11,166.29) v3(19.11,163.75) v3(19.11,161.21) v3(19.11,156.13) v3(19.11,153.59) v3(19.11,151.05) v3(19.11,145.97) v3(19.11,143.43) v3(19.11,140.89) v3(19.11,135.81) v3(19.11,133.27) v3(19.11,130.73) v3(19.11,125.65) v3(19.11,123.11) v3(19.11,120.57) v3(19.11,115.49) v3(19.11,112.95) v3(19.11,110.41) v3(19.11,105.33) v3(19.11,102.79) v3(19.11,100.25) v3(22.92,51.48) v3(22.92,48.94) v3(22.92,46.4) v3(22.92,41.32) v3(22.92,38.78) v3(22.92,31.16) v3(22.92,28.62) v3(22.92,26.08) v3(22.92,21) v3(22.92,18.46) v3(24.19,166.29) v3(24.19,163.75) v3(24.19,161.21) v3(24.19,156.13) v3(24.19,153.59) v3(24.19,151.05) v3(24.19,145.97) v3(24.19,143.43) v3(24.19,140.89) v3(24.19,135.81) v3(24.19,133.27) v3(24.19,130.73) v3(24.19,125.65) v3(24.19,123.11) v3(24.19,120.57) v3(24.19,115.49) v3(24.19,112.95) v3(24.19,110.41) v3(24.19,105.33) v3(24.19,102.79) v3(24.19,100.25) v3(25.46,51.48) v3(25.46,48.94) v3(25.46,46.4) v3(25.46,41.32) v3(25.46,38.78) v3(25.46,31.16) v3(25.46,28.62) v3(25.46,26.08) v3(25.46,21) v3(25.46,18.46) v3(26.73,166.29) v3(26.73,163.75) v3(26.73,161.21) v3(26.73,156.13) v3(26.73,153.59) v3(26.73,151.05) v3(26.73,140.89) v3(26.73,135.81) v3(26.73,133.27) v3(26.73,130.73) v3(26.73,125.65) v3(26.73,115.49) v3(26.73,112.95) v3(26.73,110.41) v3(26.73,105.33) v3(26.73,102.79) v3(26.73,100.25) v3(28,51.48) v3(28,48.94) v3(28,46.4) v3(28,41.32) v3(28,38.78) v3(28,36.24) v3(28,31.16) v3(28,28.62) v3(28,26.08) v3(28,21) v3(28,18.46) v3(29.27,166.29) v3(29.27,163.75) v3(29.27,161.21) v3(29.27,156.13) v3(29.27,153.59) v3(29.27,151.05) v3(29.27,140.89) v3(29.27,135.81) v3(29.27,133.27) v3(29.27,130.73) v3(29.27,125.65) v3(29.27,115.49) v3(29.27,112.95) v3(29.27,110.41) v3(29.27,105.33) v3(29.27,102.79) v3(29.27,100.25) v3(33.08,51.48) v3(33.08,48.94) v3(33.08,46.4) v3(33.08,41.32) v3(33.08,38.78) v3(33.08,36.24) v3(33.08,31.16) v3(33.08,28.62) v3(33.08,26.08) v3(33.08,21) v3(33.08,18.46) v3(33.08,13.38) v3(33.08,10.84) v3(34.35,166.29) v3(34.35,163.75) v3(34.35,161.21) v3(34.35,156.13) v3(34.35,153.59) v3(34.35,151.05) v3(34.35,145.97) v3(34.35,143.43) v3(34.35,140.89) v3(34.35,135.81) v3(34.35,133.27) v3(34.35,130.73) v3(34.35,125.65) v3(34.35,123.11) v3(34.35,120.57) v3(34.35,115.49) v3(34.35,112.95) v3(34.35,110.41) v3(34.35,105.33) v3(34.35,102.79) v3(34.35,100.25) v3(35.62,51.48) v3(35.62,48.94) v3(35.62,46.4) v3(35.62,41.32) v3(35.62,38.78) v3(35.62,36.24) v3(35.62,31.16) v3(35.62,28.62) v3(35.62,26.08) v3(35.62,21) v3(35.62,18.46) v3(35.62,13.38) v3(35.62,10.84) v3(36.89,166.29) v3(36.89,163.75) v3(36.89,161.21) v3(36.89,156.13) v3(36.89,153.59) v3(36.89,151.05) v3(36.89,145.97) v3(36.89,143.43) v3(36.89,140.89) v3(36.89,135.81) v3(36.89,133.27) v3(36.89,130.73) v3(36.89,125.65) v3(36.89,123.11) v3(36.89,120.57) v3(36.89,115.49) v3(36.89,112.95) v3(36.89,110.41) v3(36.89,105.33) v3(36.89,102.79) v3(36.89,100.25) v3(38.16,51.48) v3(38.16,48.94) v3(38.16,46.4) v3(38.16,41.32) v3(38.16,38.78) v3(38.16,36.24) v3(38.16,31.16) v3(38.16,28.62) v3(38.16,26.08) v3(38.16,21) v3(38.16,18.46) v3(38.16,13.38) v3(38.16,10.84) v3(41.97,166.29) v3(41.97,163.75) v3(41.97,161.21) v3(41.97,156.13) v3(41.97,153.59) v3(41.97,151.05) v3(41.97,145.97) v3(41.97,143.43) v3(41.97,140.89) v3(41.97,135.81) v3(41.97,133.27) v3(41.97,130.73) v3(41.97,125.65) v3(41.97,123.11) v3(41.97,120.57) v3(41.97,115.49) v3(41.97,112.95) v3(41.97,110.41) v3(41.97,105.33) v3(41.97,102.79) v3(41.97,100.25) v3(43.24,51.48) v3(43.24,48.94) v3(43.24,46.4) v3(43.24,41.32) v3(43.24,38.78) v3(43.24,36.24) v3(43.24,31.16) v3(43.24,28.62) v3(43.24,26.08) v3(43.24,21) v3(43.24,18.46) v3(43.24,13.38) v3(43.24,10.84) v3(44.51,166.29) v3(44.51,163.75) v3(44.51,161.21) v3(44.51,156.13) v3(44.51,153.59) v3(44.51,151.05) v3(44.51,145.97) v3(44.51,143.43) v3(44.51,140.89) v3(44.51,135.81) v3(44.51,133.27) v3(44.51,130.73) v3(44.51,125.65) v3(44.51,123.11) v3(44.51,120.57) v3(44.51,115.49) v3(44.51,112.95) v3(44.51,110.41) v3(44.51,105.33) v3(44.51,102.79) v3(44.51,100.25) v3(45.78,51.48) v3(45.78,48.94) v3(45.78,46.4) v3(45.78,41.32) v3(45.78,38.78) v3(45.78,31.16) v3(45.78,28.62) v3(45.78,26.08) v3(45.78,21) v3(45.78,18.46) v3(48.32,51.48) v3(48.32,48.94) v3(48.32,46.4) v3(48.32,41.32) v3(48.32,38.78) v3(48.32,31.16) v3(48.32,28.62) v3(48.32,26.08) v3(48.32,21) v3(48.32,18.46) v3(53.4,51.48) v3(53.4,48.94) v3(53.4,46.4) v3(53.4,41.32) v3(53.4,38.78) v3(53.4,36.24) v3(53.4,31.16) v3(53.4,28.62) v3(53.4,26.08) v3(53.4,21) v3(53.4,18.46) v3(53.4,13.38) v3(53.4,10.84) v3(55.94,51.48) v3(55.94,48.94) v3(55.94,46.4) v3(55.94,41.32) v3(55.94,38.78) v3(55.94,36.24) v3(55.94,31.16) v3(55.94,28.62) v3(55.94,26.08) v3(55.94,21) v3(55.94,18.46) v3(55.94,13.38) v3(55.94,10.84) v3(58.48,51.48) v3(58.48,48.94) v3(58.48,46.4) v3(58.48,41.32) v3(58.48,38.78) v3(58.48,36.24) v3(58.48,31.16) v3(58.48,28.62) v3(58.48,26.08) v3(58.48,21) v3(58.48,18.46) v3(58.48,13.38) v3(58.48,10.84) v3(63.56,51.48) v3(63.56,48.94) v3(63.56,46.4) v3(63.56,41.32) v3(63.56,38.78) v3(63.56,36.24) v3(63.56,31.16) v3(63.56,28.62) v3(63.56,26.08) v3(63.56,21) v3(63.56,18.46) v3(63.56,13.38) v3(63.56,10.84) v3(66.1,51.48) v3(66.1,48.94) v3(66.1,46.4) v3(66.1,41.32) v3(66.1,38.78) v3(66.1,36.24) v3(66.1,31.16) v3(66.1,28.62) v3(66.1,26.08) v3(66.1,21) v3(66.1,18.46) v3(66.1,13.38) v3(66.1,10.84) v3(68.64,51.48) v3(68.64,48.94) v3(68.64,46.4) v3(68.64,41.32) v3(68.64,38.78) v3(68.64,36.24) v3(68.64,31.16) v3(68.64,28.62) v3(68.64,26.08) v3(68.64,21) v3(68.64,18.46) v3(68.64,13.38) v3(68.64,10.84)
